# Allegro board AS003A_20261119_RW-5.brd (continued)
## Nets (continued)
D11210: D112.10 SITE1.T30(D5C1_ALERT0_N)
D11211: D112.11 SITE1.F25(PCIE_PERST_N)
D11212: D112.12 SITE1.P30(D5C1_CB6_A)
D11213: D112.13 K3.4
D11214: D112.14 SITE1.L30(D5C1_CB0_A)
D11215: D112.15 K4.4
D11216: D112.16 SITE1.B8(GPIO[33])
D11301: D113.01 R144.2
D11302: D113.02 R138.2
D11303: D113.03 R143.2
D11304: D113.04 R137.2
D11305: D113.05 R140.2
D11306: D113.06 R141.2
D11307: D113.07 R139.2
D11308: D113.08 R142.2
D11309: D113.09 R152.2
D11310: D113.10 R145.2
D11311: D113.11 R151.2
D11312: D113.12 R146.2
D11313: D113.13 R148.2
D11314: D113.14 R149.2
D11315: D113.15 R147.2
D11316: D113.16 R150.2
D11401: D114.01 SITE1.H30(D5C1_DQ19_A)
D11402: D114.02 SITE1.D32(D5C1_DQS5_A_T)
D11403: D114.03 SITE1.E30(D5C1_DQ5_A)
D11404: D114.04 SITE1.D31(D5C1_DQS5_A_C)
D11405: D114.05 SITE1.C30(D5C1_DQ3_A)
D11406: D114.06 SITE1.B31(D5C1_DQS0_A_T)
D11407: D114.07 SITE1.C27(D5C1_DQ11_A)
D11408: D114.08 SITE1.B32(D5C1_DQS0_A_C)
D11409: D114.09 SITE1.C8(GPIO[32])
D11410: D114.10 SITE1.B28(D5C1_DQS1_A_T)
D11411: D114.11 SITE1.C6(D5C0_DQ20_B)
D11412: D114.12 SITE1.B29(D5C1_DQS1_A_C)
D11413: D114.13 SITE1.C3(D5C0_DQ28_B)
D11414: D114.14 SITE1.B5(D5C0_DQS7_B_T)
D11415: D114.15 SITE1.E3(D5C0_DQ26_B)
D11416: D114.16 SITE1.B4(D5C0_DQS7_B_C)
D11501: D115.01 SITE1.A29(D5C1_DQ8_A)
D11502: D115.02 SITE1.F30(D5C1_DQ16_A)
D11503: D115.03 SITE1.A27(D5C1_DQ9_A)
D11504: D115.04 SITE1.D30(D5C1_DQ6_A)
D11505: D115.05 SITE1.A8(GPIO[34])
D11506: D115.06 SITE1.C28(D5C1_DQ12_A)
D11507: D115.07 SITE1.B7(GPIO[38])
D11508: D115.08 SITE1.C26(GPIO[29])
D11509: D115.09 SITE1.F6(D5C0_DQ6_B)
D11510: D115.10 SITE1.D4(D5C0_DQS2_B_T)
D11511: D115.11 SITE1.C7(GPIO[37])
D11512: D115.12 SITE1.D5(D5C0_DQS2_B_C)
D11513: D115.13 SITE1.C5(D5C0_DQ19_B)
D11514: D115.14 SITE1.G5(D5C0_DQS5_B_T)
D11515: D115.15 SITE1.D3(D5C0_DQ25_B)
D11516: D115.16 SITE1.G4(D5C0_DQS5_B_C)
D11601: D116.01 TR2.2 TR3.2
D11602: D116.02 SITE1.A28(D5C1_DQ10_A)
D11603: D116.03 SITE1.A31(D5C1_DQ1_A)
D11604: D116.04 SITE1.A26(GPIO[31])
D11605: D116.05 SITE1.A32(D5C1_DQ2_A)
D11606: D116.06 SITE1.A7(GPIO[39])
D11607: D116.07 SITE1.A6(D5C0_DQ22_B)
D11608: D116.08 SITE1.A5(D5C0_DQ21_B)
D11609: D116.09 SITE1.A4(D5C0_DQ23_B)
D11610: D116.10 SITE1.A30(D5C1_DQ0_A)
D11611: D116.11 SITE1.F27(D5C1_DQ25_A)
D11612: D116.12 SITE1.AA30(D5C1_CA2_B)
D11613: D116.13 SITE1.AD30(D5C1_CS0_B_N)
D11614: D116.14 SITE1.C2(D5C0_DQ27_B)
D11615: D116.15 SITE1.AF30(D5C1_CS3_B_N)
D11616: D116.16 SITE1.J30(D5C1_DQ22_A)
D11701: D117.01 SITE1.AE5(D5C0_CS0_A_N)
D11702: D117.02 SITE1.AM4(D5C0_DQS4_A_T)
D11703: D117.03 SITE1.AF5(D5C0_CS2_A_N)
D11704: D117.04 SITE1.AL4(D5C0_DQS4_A_C)
D11705: D117.05 SITE1.AG5(D5C0_DQ26_A)
D11706: D117.06 SITE1.AL7(D5C0_DQS7_A_T)
D11707: D117.07 SITE1.AH6(D5C0_DQ13_A)
D11708: D117.08 SITE1.AM7(D5C0_DQS7_A_C)
D11709: D117.09 SITE1.AH8(D5C0_DQ11_A)
D11710: D117.10 SITE1.AM9(D5C0_DQS2_A_T)
D11711: D117.11 SITE1.AG11(GPIO[12])
D11712: D117.12 SITE1.AL9(D5C0_DQS2_A_C)
D11713: D117.13 SITE1.AH11(GPIO[13])
D11714: D117.14 SITE1.AL12(D5C0_DQS5_A_T)
D11715: D117.15 SITE1.AH12(GPIO[16])
D11716: D117.16 SITE1.AM12(D5C0_DQS5_A_C)
D11801: D118.01 SITE1.AJ13(GPIO[20])
D11802: D118.02 SITE1.J4(D5C0_DQS0_B_T)
D11803: D118.03 SITE1.AJ14(GPIO[23])
D11804: D118.04 SITE1.J5(D5C0_DQS0_B_C)
D11805: D118.05 SITE1.AJ15(SPI_SCS)
D11806: D118.06 SITE1.M5(D5C0_CK1_B_T)
D11807: D118.07 SITE1.AJ16(SPI_DOUT)
D11808: D118.08 SITE1.M4(D5C0_CK1_B_C)
D11809: D118.09 SITE1.AJ17(UART_RX)
D11810: D118.10 SITE1.P5(D5C0_CK0_B_T)
D11811: D118.11 SITE1.AJ18(GPIO[26])
D11812: D118.12 SITE1.P4(D5C0_CK0_B_C)
D11813: D118.13 SITE1.AJ19(GPIO[11])
D11814: D118.14 SITE1.T5(D5C0_CK2_B_T)
D11815: D118.15 SITE1.AJ20(GPIO[8])
D11816: D118.16 SITE1.T4(D5C0_CK2_B_C)
D11901: D119.01 SITE1.AE2(D5C0_CS1_A_N)
D11902: D119.02 SITE1.Y3(D5C0_CA10_A)
D11903: D119.03 SITE1.AG6(D5C0_DQ14_A)
D11904: D119.04 SITE1.AA3(D5C0_CA9_A)
D11905: D119.05 SITE1.AL3(D5C0_CB3_A)
D11906: D119.06 SITE1.AB3(D5C0_CA7_A)
D11907: D119.07 SITE1.AL6(D5C0_DQ22_A)
D11908: D119.08 SITE1.AD3(D5C0_CA3_A)
D11909: D119.09 SITE1.AL8(D5C0_DQ19_A)
D11910: D119.10 SITE1.AE3(D5C0_CA0_A)
D11911: D119.11 SITE1.AG10(D5C0_DQ10_A)
D11912: D119.12 SITE1.AF3(D5C0_CS3_A_N)
D11913: D119.13 SITE1.AL11(D5C0_DQ6_A)
D11914: D119.14 SITE1.AG3(D5C0_DQ28_A)
D11915: D119.15 SITE1.AL13(D5C0_DQ3_A)
D11916: D119.16 SITE1.AH3(D5C0_DQ27_A)
D12001: D120.01 SITE1.AC6(D5C0_ATBPAD)
D12002: D120.02 SITE1.AD5(D5C0_PWR_GOOD)
D12003: D120.03 SITE1.AA5(D5C0_CA12_B)
D12004: D120.04 K5.4
D12005: D120.05 SITE1.H6(D5C0_DQ4_B)
D12006: D120.06 SITE1.J6(D5C0_DQ1_B)
D12007: D120.07 SITE1.K1(D5C0_DQ8_B)
D12008: D120.08 SITE1.L1(D5C0_CB1_B)
D12009: D120.09 SITE1.N6(D5C0_CS0_B_N)
D12010: D120.10 SITE1.P6(D5C0_CA1_B)
D12011: D120.11 SITE1.R1(D5C0_CB4_B)
D12012: D120.12 SITE1.U1(D5C0_ODT1_NC)
D12013: D120.13 SITE1.V1(D5C0_ODT2_NC)
D12014: D120.14 SITE1.W1(D5C0_CA11_A)
D12015: D120.15 SITE1.AA6(D5C0_CA10_B)
D12016: D120.16 SITE1.AB6(D5C0_MEMRESET_N)
D12101: D121.01 SITE1.AH13(GPIO[19])
D12102: D121.02 SITE1.AM14(D5C0_DQS0_A_T)
D12103: D121.03 SITE1.AH14(GPIO[22])
D12104: D121.04 SITE1.AL14(D5C0_DQS0_A_C)
D12105: D121.05 SITE1.AH15(TEST_EN)
D12106: D121.06 SITE1.AM19(D5C1_DQS8_B_T)
D12107: D121.07 SITE1.AH16(SPI_DIN)
D12108: D121.08 SITE1.AL19(D5C1_DQS8_B_C)
D12109: D121.09 SITE1.AH17(UART_TX)
D12110: D121.10 SITE1.AL21(D5C1_DQS3_B_T)
D12111: D121.11 SITE1.AH18(GPIO[25])
D12112: D121.12 SITE1.AM21(D5C1_DQS3_B_C)
D12113: D121.13 SITE1.AH19(GPIO[10])
D12114: D121.14 SITE1.AM24(D5C1_DQS6_B_T)
D12115: D121.15 SITE1.AH20(GPIO[7])
D12116: D121.16 SITE1.AL24(D5C1_DQS6_B_C)
D12201: D122.01 SITE1.AJ21(GPIO[5])
D12202: D122.02 SITE1.V5(D5C0_CK3_B_T)
D12203: D122.03 SITE1.AJ22(GPIO[2])
D12204: D122.04 SITE1.V4(D5C0_CK3_B_C)
D12205: D122.05 SITE1.AJ23(D5C1_DQ23_B)
D12206: D122.06 SITE1.AJ4(D5C0_DQS3_A_T)
D12207: D122.07 SITE1.AJ27(D5C1_DQ16_B)
D12208: D122.08 SITE1.AH4(D5C0_DQS3_A_C)
D12209: D122.09 SITE1.AJ28(D5C1_DQ7_B)
D12210: D122.10 SITE1.AH7(D5C0_DQS6_A_T)
D12211: D122.11 SITE1.AG29(D5C1_DQ6_B)
D12212: D122.12 SITE1.AJ7(D5C0_DQS6_A_C)
D12213: D122.13 SITE1.AE29(D5C1_ODT3_NC)
D12214: D122.14 SITE1.AJ9(D5C0_DQS1_A_T)
D12215: D122.15 SITE1.AD29(D5C1_CA13_A)
D12216: D122.16 SITE1.AH9(D5C0_DQS1_A_C)
D12301: D123.01 SITE1.AG15(DDR_SCL)
D12302: D123.02 SITE1.AK3(D5C0_CB4_A)
D12303: D123.03 SITE1.AG16(SPI_SCK)
D12304: D123.04 SITE1.AK4(D5C0_CB1_A)
D12305: D123.05 SITE1.AL17(SLV_SDA)
D12306: D123.06 SITE1.AK5(D5C0_CB2_A)
D12307: D123.07 SITE1.AG18(GPIO[24])
D12308: D123.08 SITE1.AK6(D5C0_DQ23_A)
D12309: D123.09 SITE1.AL20(D5C1_DQ28_B)
D12310: D123.10 SITE1.AK8(D5C0_DQ20_A)
D12311: D123.11 SITE1.AL22(D5C1_DQ25_B)
D12312: D123.12 SITE1.AK9(D5C0_DQ17_A)
D12313: D123.13 SITE1.AG23(D5C1_DQ21_B)
D12314: D123.14 SITE1.AK10(D5C0_DQ18_A)
D12315: D123.15 SITE1.AL25(D5C1_DQ12_B)
D12316: D123.16 SITE1.AK11(D5C0_DQ7_A)
D12401: D124.01 SITE1.AC1(D5C0_CA5_A)
D12402: D124.02 SITE1.AE6(D5C0_CA2_A)
D12403: D124.03 SITE1.AF6(D5C0_ALERT1_N)
D12404: D124.04 SITE1.AG1(D5C0_DQ30_A)
D12405: D124.05 SITE1.AH1(D5C0_DQ29_A)
D12406: D124.06 SITE1.AJ1(D5C0_DQ31_A)
D12407: D124.07 SITE1.AK1(D5C0_CB7_A)
D12408: D124.08 SITE1.AL1(D5C0_CB6_A)
D12409: D124.09 SITE1.AM1(D5C0_CB5_A)
D12410: D124.10 SITE1.AM5(D5C0_CB0_A)
D12411: D124.11 SITE1.AM6(D5C0_DQ21_A)
D12412: D124.12 SITE1.AG8(D5C0_DQ12_A)
D12413: D124.13 SITE1.AG9(D5C0_DQ9_A)
D12414: D124.14 SITE1.AM10(D5C0_DQ16_A)
D12415: D124.15 SITE1.AM11(D5C0_DQ5_A)
D12416: D124.16 SITE1.AG13(GPIO[18])
D12501: D125.01 SITE1.D7(GPIO[36])
D12502: D125.02 SITE1.B2(D5C0_DQS8_B_T)
D12503: D125.03 SITE1.A2(D5C0_DQ30_B)
D12504: D125.04 SITE1.B1(D5C0_DQS8_B_C)
D12505: D125.05 SITE1.A1(D5C0_DQ29_B)
D12506: D125.06 SITE1.D1(D5C0_DQS3_B_T)
D12507: D125.07 SITE1.E1(D5C0_DQ24_B)
D12508: D125.08 SITE1.D2(D5C0_DQS3_B_C)
D12509: D125.09 SITE1.F1(D5C0_DQ13_B)
D12510: D125.10 SITE1.G2(D5C0_DQS6_B_T)
D12511: D125.11 SITE1.E7(GPIO[35])
D12512: D125.12 SITE1.G1(D5C0_DQS6_B_C)
D12513: D125.13 SITE1.E6(D5C0_DQ18_B)
D12514: D125.14 SITE1.J1(D5C0_DQS1_B_T)
D12515: D125.15 SITE1.F5(D5C0_DQ5_B)
D12516: D125.16 SITE1.J2(D5C0_DQS1_B_C)
D12601: D126.01 SITE1.J3(D5C0_DQ9_B)
D12602: D126.02 SITE1.M2(D5C0_DQS4_B_T)
D12603: D126.03 SITE1.E4(D5C0_DQ16_B)
D12604: D126.04 SITE1.M1(D5C0_DQS4_B_C)
D12605: D126.05 SITE1.K4(D5C0_DQ0_B)
D12606: D126.06 SITE1.P2(D5C0_DQS9_B_T)
D12607: D126.07 SITE1.N4(D5C0_PAR_B)
D12608: D126.08 SITE1.P1(D5C0_DQS9_B_C)
D12609: D126.09 SITE1.U4(D5C0_CA4_B)
D12610: D126.10 SITE1.Y1(D5C0_CK2_A_T)
D12611: D126.11 SITE1.Y4(D5C0_CA11_B)
D12612: D126.12 SITE1.Y2(D5C0_CK2_A_C)
D12613: D126.13 SITE1.AB4(D5C0_ALERT0_N)
D12614: D126.14 SITE1.AB2(D5C0_CK1_A_T)
D12615: D126.15 SITE1.AD4(D5C0_CA4_A)
D12616: D126.16 SITE1.AB1(D5C0_CK1_A_C)
D12701: D127.01 SITE1.H2(D5C0_DQ11_B)
D12702: D127.02 SITE1.D6(D5C0_DQ17_B)
D12703: D127.03 SITE1.L3(D5C0_CB3_B)
D12704: D127.04 SITE1.F4(D5C0_DQ7_B)
D12705: D127.05 SITE1.P3(D5C0_CB5_B)
D12706: D127.06 SITE1.M6(D5C0_CS2_B_N)
D12707: D127.07 SITE1.T3(D5C0_CID1_NC)
D12708: D127.08 SITE1.T6(D5C0_CA2_B)
D12709: D127.09 SITE1.V3(D5C0_CA13_A)
D12710: D127.10 SITE1.W6(D5C0_CA7_B)
D12711: D127.11 SITE1.T2(D5C0_CID0_NC)
D12712: D127.12 SITE1.AA4(D5C0_CA13_B)
D12713: D127.13 SITE1.W2(D5C0_CA12_A)
D12714: D127.14 SITE1.AC4(D5C0_PAR_A)
D12715: D127.15 SITE1.AC2(D5C0_CA6_A)
D12716: D127.16 SITE1.AE4(D5C0_CA1_A)
D12801: D128.01 SITE1.F2(D5C0_DQ14_B)
D12802: D128.02 SITE1.K3(D5C0_DQ10_B)
D12803: D128.03 SITE1.K6(D5C0_DQ2_B)
D12804: D128.04 SITE1.N3(D5C0_CB0_B)
D12805: D128.05 SITE1.L2(D5C0_CB2_B)
D12806: D128.06 SITE1.R3(D5C0_CB6_B)
D12807: D128.07 SITE1.N2(D5C0_CB7_B)
D12808: D128.08 SITE1.U3(D5C0_CID2_NC)
D12809: D128.09 SITE1.R6(D5C0_CA0_B)
D12810: D128.10 SITE1.W3(D5C0_ODT0_NC)
D12811: D128.11 SITE1.H3(D5C0_DQ12_B)
D12812: D128.12 SITE1.U2(D5C0_ODT3_NC)
D12813: D128.13 SITE1.F3(D5C0_DQ15_B)
D12814: D128.14 SITE1.AA2(D5C0_CA8_A)
D12815: D128.15 SITE1.AG22(GPIO[0])
D12816: D128.16 SITE1.AG4(D5C0_DQ25_A)
D12901: D129.01 SITE1.H5(D5C0_DQ3_B)
D12902: D129.02 SITE1.AD1(D5C0_CK0_A_T)
D12903: D129.03 SITE1.L5(D5C0_CS1_B_N)
D12904: D129.04 SITE1.AD2(D5C0_CK0_A_C)
D12905: D129.05 SITE1.L6(D5C0_CS3_B_N)
D12906: D129.06 SITE1.AF2(D5C0_CK3_A_T)
D12907: D129.07 SITE1.R5(D5C0_CA3_B)
D12908: D129.08 SITE1.AF1(D5C0_CK3_A_C)
D12909: D129.09 SITE1.U6(D5C0_CA5_B)
D12910: D129.10 SITE1.AH2(D5C0_DQS8_A_T)
D12911: D129.11 SITE1.V6(D5C0_CA6_B)
D12912: D129.12 SITE1.AJ2(D5C0_DQS8_A_C)
D12913: D129.13 SITE1.W5(D5C0_CA9_B)
D12914: D129.14 SITE1.AL2(D5C0_DQS9_A_T)
D12915: D129.15 SITE1.Y5(D5C0_CA8_B)
D12916: D129.16 SITE1.AM2(D5C0_DQS9_A_C)
D13001: D130.01 SITE1.AJ5(D5C0_DQ24_A)
D13002: D130.02 SITE1.AJ6(D5C0_DQ15_A)
D13003: D130.03 SITE1.AJ10(D5C0_DQ8_A)
D13004: D130.04 SITE1.AJ11(GPIO[14])
D13005: D130.05 SITE1.AJ12(GPIO[17])
D13006: D130.06 SITE1.A3(D5C0_DQ31_B)
D13007: D130.07
D13008: D130.08
D13009: D130.09
D13010: D130.10
D13011: D130.11
D13012: D130.12
D13013: D130.13
D13014: D130.14
D13015: D130.15
D13016: D130.16
D13101: D131.01
D13102: D131.02
D13103: D131.03
D13104: D131.04
D13105: D131.05
D13106: D131.06
D13107: D131.07
D13108: D131.08
D13109: D131.09
D13110: D131.10
D13111: D131.11
D13112: D131.12
D13113: D131.13
D13114: D131.14
D13115: D131.15
D13116: D131.16
D13201: D132.01
D13202: D132.02
D13203: D132.03
D13204: D132.04
D13205: D132.05
D13206: D132.06
D13207: D132.07
D13208: D132.08
D13209: D132.09
D13210: D132.10
D13211: D132.11
D13212: D132.12
D13213: D132.13
D13214: D132.14
D13215: D132.15
D13216: D132.16
D21701: D217.01
D21702: D217.02
D21703: D217.03
D21704: D217.04
D21705: D217.05
D21706: D217.06
D21707: D217.07
D21708: D217.08
D21709: D217.09
D21710: D217.10
D21711: D217.11
D21712: D217.12
D21713: D217.13
D21714: D217.14
D21715: D217.15
D21716: D217.16
D21801: D218.01
D21802: D218.02
D21803: D218.03
D21804: D218.04
D21805: D218.05
D21806: D218.06
D21807: D218.07
D21808: D218.08
D21809: D218.09
D21810: D218.10
D21811: D218.11
D21812: D218.12
D21813: D218.13
D21814: D218.14
D21815: D218.15
D21816: D218.16
D21901: D219.01
D21902: D219.02
D21903: D219.03
D21904: D219.04
D21905: D219.05
D21906: D219.06
D21907: D219.07
D21908: D219.08
D21909: D219.09
D21910: D219.10
D21911: D219.11
D21912: D219.12
D21913: D219.13
D21914: D219.14
D21915: D219.15
D21916: D219.16
D22001: D220.01
D22002: D220.02
D22003: D220.03
D22004: D220.04
D22005: D220.05
D22006: D220.06
D22007: D220.07
D22008: D220.08
D22009: D220.09
D22010: D220.10
D22011: D220.11
D22012: D220.12
D22013: D220.13
D22014: D220.14
D22015: D220.15
D22016: D220.16
D22101: D221.01
D22102: D221.02
D22103: D221.03
D22104: D221.04
D22105: D221.05
D22106: D221.06
D22107: D221.07
D22108: D221.08
D22109: D221.09
D22110: D221.10
D22111: D221.11
D22112: D221.12
D22113: D221.13
D22114: D221.14
D22115: D221.15
D22116: D221.16
D22201: D222.01
D22202: D222.02
D22203: D222.03
D22204: D222.04
D22205: D222.05
D22206: D222.06
D22207: D222.07
D22208: D222.08
D22209: D222.09
D22210: D222.10
D22211: D222.11
D22212: D222.12
D22213: D222.13
D22214: D222.14
D22215: D222.15
D22216: D222.16
D22301: D223.01
D22302: D223.02
D22303: D223.03
D22304: D223.04
D22305: D223.05
D22306: D223.06
D22307: D223.07
D22308: D223.08
D22309: D223.09
D22310: D223.10
D22311: D223.11
D22312: D223.12
D22313: D223.13
D22314: D223.14
D22315: D223.15
D22316: D223.16
D22401: D224.01
D22402: D224.02
D22403: D224.03
D22404: D224.04
D22405: D224.05
D22406: D224.06
D22407: D224.07
D22408: D224.08
D22409: D224.09
D22410: D224.10
D22411: D224.11
D22412: D224.12
D22413: D224.13
D22414: D224.14
D22415: D224.15
D22416: D224.16
D30101: D301.01
D30102: D301.02
D30103: D301.03
D30104: D301.04
D30105: D301.05
D30106: D301.06
D30107: D301.07
D30108: D301.08
D30109: D301.09
D30110: D301.10
D30111: D301.11
D30112: D301.12
D30113: D301.13
D30114: D301.14
D30115: D301.15
D30116: D301.16
D30201: D302.01
D30202: D302.02
D30203: D302.03
D30204: D302.04
D30205: D302.05
D30206: D302.06
D30207: D302.07
D30208: D302.08
D30209: D302.09
D30210: D302.10
D30211: D302.11
D30212: D302.12
D30213: D302.13
D30214: D302.14
D30215: D302.15
D30216: D302.16
D30301: D303.01
D30302: D303.02
D30303: D303.03
D30304: D303.04
D30305: D303.05
D30306: D303.06
D30307: D303.07
D30308: D303.08
D30309: D303.09
D30310: D303.10
D30311: D303.11
D30312: D303.12
D30313: D303.13
D30314: D303.14
D30315: D303.15
D30316: D303.16
D30401: D304.01
D30402: D304.02
D30403: D304.03
D30404: D304.04
D30405: D304.05
D30406: D304.06
D30407: D304.07
D30408: D304.08
D30409: D304.09
D30410: D304.10
D30411: D304.11
D30412: D304.12
D30413: D304.13
D30414: D304.14
D30415: D304.15
D30416: D304.16
D30501: D305.01
D30502: D305.02
D30503: D305.03
D30504: D305.04
D30505: D305.05
D30506: D305.06
D30507: D305.07
D30508: D305.08
D30509: D305.09
D30510: D305.10
D30511: D305.11
D30512: D305.12
D30513: D305.13
D30514: D305.14
D30515: D305.15
D30516: D305.16
D30601: D306.01
D30602: D306.02
D30603: D306.03
D30604: D306.04
D30605: D306.05
D30606: D306.06
D30607: D306.07
D30608: D306.08
D30609: D306.09
D30610: D306.10
D30611: D306.11
D30612: D306.12
D30613: D306.13
D30614: D306.14
D30615: D306.15
D30616: D306.16
D30701: D307.01
D30702: D307.02
D30703: D307.03
D30704: D307.04
D30705: D307.05
D30706: D307.06
D30707: D307.07
D30708: D307.08
D30709: D307.09
D30710: D307.10
D30711: D307.11
D30712: D307.12
D30713: D307.13
D30714: D307.14
D30715: D307.15
D30716: D307.16
D30801: D308.01
D30802: D308.02
D30803: D308.03
D30804: D308.04
D30805: D308.05
D30806: D308.06
D30807: D308.07
D30808: D308.08
D30809: D308.09
D30810: D308.10
D30811: D308.11
D30812: D308.12
D30813: D308.13
D30814: D308.14
D30815: D308.15
D30816: D308.16
D30901: D309.01
D30902: D309.02
D30903: D309.03
D30904: D309.04
D30905: D309.05
D30906: D309.06
D30907: D309.07
D30908: D309.08
D30909: D309.09
D30910: D309.10
D30911: D309.11
D30912: D309.12
D30913: D309.13
D30914: D309.14
D30915: D309.15
D30916: D309.16
D31001: D310.01
D31002: D310.02
D31003: D310.03
D31004: D310.04
D31005: D310.05
D31006: D310.06
D31007: D310.07
D31008: D310.08
D31009: D310.09
D31010: D310.10
D31011: D310.11
D31012: D310.12
D31013: D310.13
D31014: D310.14
D31015: D310.15
D31016: D310.16
D31101: D311.01
D31102: D311.02
D31103: D311.03
D31104: D311.04
D31105: D311.05
D31106: D311.06
D31107: D311.07
D31108: D311.08
D31109: D311.09
D31110: D311.10
D31111: D311.11
D31112: D311.12
D31113: D311.13
D31114: D311.14
D31115: D311.15
D31116: D311.16
D31201: D312.01
D31202: D312.02
D31203: D312.03
D31204: D312.04
D31205: D312.05
D31206: D312.06
D31207: D312.07
D31208: D312.08
D31209: D312.09
D31210: D312.10
D31211: D312.11
D31212: D312.12
D31213: D312.13
D31214: D312.14
D31215: D312.15
D31216: D312.16
D31301: D313.01
D31302: D313.02
D31303: D313.03
D31304: D313.04
D31305: D313.05
D31306: D313.06
D31307: D313.07
D31308: D313.08
D31309: D313.09
D31310: D313.10
D31311: D313.11
D31312: D313.12
D31313: D313.13
D31314: D313.14
D31315: D313.15
D31316: D313.16
D31401: D314.01
D31402: D314.02
D31403: D314.03
D31404: D314.04
D31405: D314.05
D31406: D314.06
D31407: D314.07
D31408: D314.08
D31409: D314.09
D31410: D314.10
D31411: D314.11
D31412: D314.12
D31413: D314.13
D31414: D314.14
D31415: D314.15
D31416: D314.16
D31501: D315.01
D31502: D315.02
D31503: D315.03
D31504: D315.04
D31505: D315.05
D31506: D315.06
D31507: D315.07
D31508: D315.08
D31509: D315.09
D31510: D315.10
D31511: D315.11
D31512: D315.12
D31513: D315.13
D31514: D315.14
D31515: D315.15
D31516: D315.16
D31601: D316.01
D31602: D316.02
D31603: D316.03
D31604: D316.04
D31605: D316.05
D31606: D316.06
D31607: D316.07
D31608: D316.08
D31609: D316.09
D31610: D316.10
D31611: D316.11
D31612: D316.12
D31613: D316.13
D31614: D316.14
D31615: D316.15
D31616: D316.16
D31701: D317.01
D31702: D317.02
D31703: D317.03
D31704: D317.04
D31705: D317.05
D31706: D317.06
D31707: D317.07
D31708: D317.08
D31709: D317.09
D31710: D317.10
D31711: D317.11
D31712: D317.12
D31713: D317.13
D31714: D317.14
D31715: D317.15
D31716: D317.16
D31801: D318.01
D31802: D318.02
D31803: D318.03
D31804: D318.04
D31805: D318.05
D31806: D318.06
D31807: D318.07
D31808: D318.08
D31809: D318.09
D31810: D318.10
D31811: D318.11
D31812: D318.12
D31813: D318.13
D31814: D318.14
D31815: D318.15
D31816: D318.16
D31901: D319.01
D31902: D319.02
D31903: D319.03
D31904: D319.04
D31905: D319.05
D31906: D319.06
D31907: D319.07
D31908: D319.08
D31909: D319.09
D31910: D319.10
D31911: D319.11
D31912: D319.12
D31913: D319.13
D31914: D319.14
D31915: D319.15
D31916: D319.16
D32001: D320.01
D32002: D320.02
D32003: D320.03
D32004: D320.04
D32005: D320.05
D32006: D320.06
D32007: D320.07
D32008: D320.08
D32009: D320.09
D32010: D320.10
D32011: D320.11
D32012: D320.12
D32013: D320.13
D32014: D320.14
D32015: D320.15
D32016: D320.16
D32101: D321.01
D32102: D321.02
D32103: D321.03
D32104: D321.04
D32105: D321.05
D32106: D321.06
D32107: D321.07
D32108: D321.08
D32109: D321.09
D32110: D321.10
D32111: D321.11
D32112: D321.12
D32113: D321.13
D32114: D321.14
D32115: D321.15
D32116: D321.16
D32201: D322.01
D32202: D322.02
D32203: D322.03
D32204: D322.04
D32205: D322.05
D32206: D322.06
D32207: D322.07
D32208: D322.08
D32209: D322.09
D32210: D322.10
D32211: D322.11
D32212: D322.12
D32213: D322.13
D32214: D322.14
D32215: D322.15
D32216: D322.16
D32301: D323.01
D32302: D323.02
D32303: D323.03
D32304: D323.04
D32305: D323.05
D32306: D323.06
D32307: D323.07
D32308: D323.08
D32309: D323.09
D32310: D323.10
D32311: D323.11
D32312: D323.12
D32313: D323.13
D32314: D323.14
D32315: D323.15
D32316: D323.16
GPDPS1_1F: DPS1.A03 DPS1.B03 DPS1.C03 R224.2 R225.2 R226.2 R232.2
GPDPS1_1GRD: DPS1.B02
GPDPS1_1GS: DPS1.A02 R216.2
GPDPS1_1S: DPS1.C02 R231.2
GPDPS1_2F: DPS1.A07 DPS1.B07 DPS1.C07 R70.2
GPDPS1_2GRD: DPS1.B06
GPDPS1_2GS: DPS1.A06 R67.2
GPDPS1_2S: DPS1.C06 R71.2
GPDPS1_3F: DPS1.A13 DPS1.B13 DPS1.C13 R5.2
GPDPS1_3GRD: DPS1.B12
GPDPS1_3GS: DPS1.A12 R4.2
GPDPS1_3S: DPS1.C12 R6.2
GPDPS1_4F: DPS1.A17 DPS1.B17 DPS1.C17 R10.2
GPDPS1_4GRD: DPS1.B16
GPDPS1_4GS: DPS1.A16 R7.2
GPDPS1_4S: DPS1.C16 R11.2
GPDPS1_TR+: DPS1.A09
GPDPS1_TRVB-: DPS1.B09 SB1.2
GPDPS1_VB+: DPS1.C09
GPDPS2_1F: DPS2.A03 DPS2.B03 DPS2.C03 R16.2 R162.2
GPDPS2_1GRD: DPS2.B02
GPDPS2_1GS: DPS2.A02 R13.2
GPDPS2_1S: DPS2.C02 R17.2
GPDPS2_2F: DPS2.A07 DPS2.B07 DPS2.C07 R22.2
GPDPS2_2GRD: DPS2.B06
GPDPS2_2GS: DPS2.A06 R20.2
GPDPS2_2S: DPS2.C06 R23.2
GPDPS2_3F: DPS2.A13 DPS2.B13 DPS2.C13 R52.2 R64.2 R189.2 R194.2
GPDPS2_3GRD: DPS2.B12
GPDPS2_3GS: DPS2.A12 R62.2 R186.2 R191.2
GPDPS2_3S: DPS2.C12 R65.2
GPDPS2_4F: DPS2.A17 DPS2.B17 DPS2.C17 R204.2 R205.2 R206.2 R211.2
GPDPS2_4GRD: DPS2.B16
GPDPS2_4GS: DPS2.A16 R197.2
GPDPS2_4S: DPS2.C16 R212.2
GPDPS2_TR+: DPS2.A09
GPDPS2_TRVB-: DPS2.B09 SB13.2
GPDPS2_VB+: DPS2.C09
GPDPS3_1F: DPS3.A03 DPS3.B03 DPS3.C03 R77.2 R168.2 R169.2 R170.2
GPDPS3_1GRD: DPS3.B02
GPDPS3_1GS: DPS3.A02 R73.2
GPDPS3_1S: DPS3.C02 R76.2
GPDPS3_2F: DPS3.A07 DPS3.B07 DPS3.C07 R28.2 R34.2 R163.2 R164.2
GPDPS3_2GRD: DPS3.B06
GPDPS3_2GS: DPS3.A06 R26.2
GPDPS3_2S: DPS3.C06 R29.2
GPDPS3_3F: DPS3.A13 DPS3.B13 DPS3.C13 R40.2 R46.2
GPDPS3_3GRD: DPS3.B12
GPDPS3_3GS: DPS3.A12 R38.2
GPDPS3_3S: DPS3.C12 R41.2
GPDPS3_4F: DPS3.A17 DPS3.B17 DPS3.C17 R58.2
GPDPS3_4GRD: DPS3.B16
GPDPS3_4GS: DPS3.A16 R56.2
GPDPS3_4S: DPS3.C16 R59.2
GPDPS3_TR+: DPS3.A09
GPDPS3_TRVB-: DPS3.B09 SB14.2
GPDPS3_VB+: DPS3.C09
GPDPS4_1F: DPS4.A03 DPS4.B03 DPS4.C03
GPDPS4_1GRD: DPS4.B02
GPDPS4_1GS: DPS4.A02
GPDPS4_1S: DPS4.C02
GPDPS4_2F: DPS4.A07 DPS4.B07 DPS4.C07
GPDPS4_2GRD: DPS4.B06
GPDPS4_2GS: DPS4.A06
GPDPS4_2S: DPS4.C06
GPDPS4_3F: DPS4.A13 DPS4.B13 DPS4.C13
GPDPS4_3GRD: DPS4.B12
GPDPS4_3GS: DPS4.A12
GPDPS4_3S: DPS4.C12
GPDPS4_4F: DPS4.A17 DPS4.B17 DPS4.C17
GPDPS4_4GRD: DPS4.B16
GPDPS4_4GS: DPS4.A16
GPDPS4_4S: DPS4.C16
GPDPS4_TR+: DPS4.A09
GPDPS4_TRVB-: DPS4.B09 SB16.2
GPDPS4_VB+: DPS4.C09
GPDPS7_1F: DPS7.A03 DPS7.B03 DPS7.C03
GPDPS7_1GRD: DPS7.B02
GPDPS7_1GS: DPS7.A02
GPDPS7_1S: DPS7.C02
GPDPS7_2F: DPS7.A07 DPS7.B07 DPS7.C07
GPDPS7_2GRD: DPS7.B06
GPDPS7_2GS: DPS7.A06
GPDPS7_2S: DPS7.C06
GPDPS7_3F: DPS7.A13 DPS7.B13 DPS7.C13
GPDPS7_3GRD: DPS7.B12
GPDPS7_3GS: DPS7.A12
GPDPS7_3S: DPS7.C12
GPDPS7_4F: DPS7.A17 DPS7.B17 DPS7.C17
GPDPS7_4GRD: DPS7.B16
GPDPS7_4GS: DPS7.A16
GPDPS7_4S: DPS7.C16
GPDPS7_TR+: DPS7.A09
GPDPS7_TRVB-: DPS7.B09 SB19.2
GPDPS7_VB+: DPS7.C09
GPDPS8_1F: DPS8.A03 DPS8.B03 DPS8.C03
GPDPS8_1GRD: DPS8.B02
GPDPS8_1GS: DPS8.A02
GPDPS8_1S: DPS8.C02
GPDPS8_2F: DPS8.A07 DPS8.B07 DPS8.C07
GPDPS8_2GRD: DPS8.B06
GPDPS8_2GS: DPS8.A06
GPDPS8_2S: DPS8.C06
GPDPS8_3F: DPS8.A13 DPS8.B13 DPS8.C13
GPDPS8_3GRD: DPS8.B12
GPDPS8_3GS: DPS8.A12
GPDPS8_3S: DPS8.C12
GPDPS8_4F: DPS8.A17 DPS8.B17 DPS8.C17
GPDPS8_4GRD: DPS8.B16
GPDPS8_4GS: DPS8.A16
GPDPS8_4S: DPS8.C16
GPDPS8_TR+: DPS8.A09
GPDPS8_TRVB-: DPS8.B09 SB15.2
GPDPS8_VB+: DPS8.C09
S1_CBIT001: DV2.2(B) K1.9(V-)
S1_CBIT002: DV3.2(B) K2.9(V-)
S1_CBIT003: DV4.2(B) K3.8(V-)
S1_CBIT004: DV5.2(B) K4.8(V-)
S1_CBIT005: DV6.2(B) K5.8(V-)
S1_CBIT006: DV7.2(B) K6.8(V-)
S1_CBIT007: DV8.2(B) K7.8(V-)
S1_CBIT008: DV9.2(B) K8.8(V-)
S1_CBIT009: DV10.2(B) K9.8(V-)
S1_CBIT010: DV11.2(B) K10.8(V-)
S1_CBIT011: DV12.2(B) K11.8(V-)
S1_CBIT012: DV13.2(B) K12.8(V-)
S1_CSDPS001F: R2.2
S1_CSDPS001GS: R3.2
S1_CSDPS001S: R1.2
S1_CSDPS002F: R9.2
S1_CSDPS002GS: R8.2
S1_CSDPS002S: R12.2
S1_CSDPS003-1F: R15.2 R153.2
S1_CSDPS003-1GS: R14.2
S1_CSDPS003-1S: R18.2
S1_CSDPS004-1F: R21.2
S1_CSDPS004-1GS: R19.2
S1_CSDPS004-1S: R24.2
S1_CSDPS005-1F: R27.2 R154.2
S1_CSDPS005-1GS: R25.2
S1_CSDPS005-1S: R30.2
S1_CSDPS006-1F: R33.2 R155.2
S1_CSDPS006-1GS: R31.2
S1_CSDPS006-1S: R36.2
S1_CSDPS007-1F: R39.2
S1_CSDPS007-1GS: R37.2
S1_CSDPS007-1S: R42.2
S1_CSDPS008-1F: R45.2
S1_CSDPS008-1GS: R43.2
S1_CSDPS008-1S: R48.2
S1_CSDPS009F: R51.2
S1_CSDPS009GS: R49.2
S1_CSDPS009S: R54.2
S1_CSDPS010-1F: R57.2
S1_CSDPS010-1GS: R55.2
S1_CSDPS010-1S: R60.2
S1_CSDPS011F: R63.2
S1_CSDPS011GS: R61.2
S1_CSDPS011S: R66.2
S1_CSDPS012F: R69.2
S1_CSDPS012GS: R68.2
S1_CSDPS012S: R72.2
S1_CSDPS013-1F: R75.2 R156.2 R157.2 R158.2
S1_CSDPS013-1GS: R74.2
S1_CSDPS013-1S: R78.2
S1_CSDPS014-1F: R198.2 R199.2 R200.2 R210.2
S1_CSDPS014-1GS: R196.2 R217.2
S1_CSDPS014-1S: R213.2
S1_CSDPS015-1F: R218.2 R219.2 R220.2 R230.2
S1_CSDPS015-1S: R233.2
S1_CSDPS016F: R187.2
S1_CSDPS016GS: R188.2
S1_CSDPS016S: R190.2
S1_CSDPS017F: R192.2
S1_CSDPS017GS: R193.2
S1_CSDPS017S: R195.2
S1_D5C0_ZQPAD: R112.1 R113.1 SITE1.AC5(D5C0_ZQPAD)
S1_D5C0_ZQPAD_A: K5.3 R113.2
S1_D5C1_ZQPAD: R114.1 R115.1 SITE1.M27(D5C1_ZQPAD)
S1_D5C1_ZQPAD_A: K6.3 R115.2
S1_DPS1: C81.1 C82.1 C216.1 C217.1 C218.1 C219.1 C220.1 R57.1 R58.1 R59.1 R60.1 S1_DPS1.1(TP) SITE1.T12(VAA[1]) SITE1.T22(VAA[2])
S1_DPS3: C83.1 C221.1 C222.1 C223.1 C224.1 C225.1 R63.1 R64.1 R65.1 R66.1 S1_DPS3.1(TP) SITE1.AE19(VCC18V_POR)
S1_DPS4: C84.1 C226.1 C227.1 C228.1 C229.1 C230.1 R69.1 R70.1 R71.1 R72.1 S1_DPS4.1(TP) SITE1.V16(VCC18V_TSENSOR)
S1_DPS5: C58.1 C59.1 C60.1 C61.1 C62.1 C63.1 C64.1 C65.1 C66.1 C67.1 C68.1 C69.1 C201.1 C202.1 C203.1 C204.1 C205.1 R39.1 R40.1 R41.1 R42.1 S1_DPS5.1(TP) SITE1.AA11(VDD_DDR_CORE_0[1]) SITE1.AB12(VDD_DDR_CORE_0[2]) SITE1.AC11(VDD_DDR_CORE_0[3]) SITE1.AD12(VDD_DDR_CORE_0[4]) SITE1.N11(VDD_DDR_CORE_0[5]) SITE1.P12(VDD_DDR_CORE_0[6]) SITE1.R11(VDD_DDR_CORE_0[7]) SITE1.R13(VDD_DDR_CORE_0[8]) SITE1.U11(VDD_DDR_CORE_0[9]) SITE1.V12(VDD_DDR_CORE_0[10]) SITE1.W11(VDD_DDR_CORE_0[11]) SITE1.Y12(VDD_DDR_CORE_0[12])
S1_DPS7: C70.1 C71.1 C72.1 C73.1 C74.1 C75.1 C76.1 C77.1 C78.1 C79.1 C80.1 C206.1 C207.1 C208.1 C209.1 C210.1 R45.1 R46.1 R48.1 S1_DPS7.1(TP) SITE1.AA21(VDD_DDR_CORE_1[1]) SITE1.AB22(VDD_DDR_CORE_1[2]) SITE1.AC21(VDD_DDR_CORE_1[3]) SITE1.AD22(VDD_DDR_CORE_1[4]) SITE1.N21(VDD_DDR_CORE_1[5]) SITE1.P22(VDD_DDR_CORE_1[6]) SITE1.R21(VDD_DDR_CORE_1[7]) SITE1.U21(VDD_DDR_CORE_1[8]) SITE1.V22(VDD_DDR_CORE_1[9]) SITE1.W21(VDD_DDR_CORE_1[10]) SITE1.Y22(VDD_DDR_CORE_1[11])
S1_DPS9: C1.1 C2.1 C3.1 C4.1 C5.1 C6.1 R1.1 R2.1 R5.1 R6.1 S1_DPS9.1(TP) SITE1.U17(VDDHV)
S1_DPS10: C7.1 C8.1 C9.1 C10.1 C11.1 C12.1 C13.1 C14.1 R9.1 R10.1 R11.1 R12.1 S1_DPS10.1(TP) SITE1.AE13(VDDPST[1]) SITE1.AE15(VDDPST[2]) SITE1.AE17(VDDPST[3])
S1_DPS11: BD18.1 C249.1 C250.1 C291.1 C292.1 C293.1 C294.1 C295.1 C416.1 C417.1 C467.1 C468.1 C469.1 K10.3 K11.3 K12.3 R187.1 R189.1 R190.1 R253.2 R254.2 S1_DPS11.1(TP) U1.6(VDD) U2.6(VDD) U4.6(VDD)
S1_DPS12: C251.1 C296.1 C297.1 C298.1 C299.1 C300.1 C418.1 OSC1.4(VDD) R116.2 R192.1 R194.1 R195.1 S1_DPS12.1(TP)
S1_DPS17: BD13.1 BD14.1 C26.1 C27.1 C28.1 C29.1 C30.1 C31.1 C32.1 C33.1 C34.1 C35.1 C36.1 C37.1 C181.1 C182.1 C183.1 C184.1 C185.1 C286.1 R17.1 R18.1 S1_DPS17.1(TP) SITE1.L13(VDD_PCIE[1]) SITE1.L15(VDD_PCIE[2]) SITE1.L17(VDD_PCIE[3]) SITE1.L19(VDD_PCIE[4]) SITE1.M12(VDD_PCIE[5]) SITE1.M14(VDD_PCIE[6]) SITE1.M16(VDD_PCIE[7]) SITE1.M18(VDD_PCIE[8]) SITE1.M20(VDD_PCIE[9]) SITE1.M22(VDD_PCIE[10]) SITE1.N15(VDD_PCIE[11]) SITE1.N17(VDD_PCIE[12])
S1_DPS20: BD15.1 BD16.1 C38.1 C39.1 C40.1 C41.1 C42.1 C43.1 C44.1 C45.1 C46.1 C47.1 C186.1 C187.1 C188.1 C189.1 C190.1 C289.1 R23.1 R24.1 S1_DPS20.1(TP) SITE1.J11(VDDH_PCIE[1]) SITE1.J21(VDDH_PCIE[2]) SITE1.K12(VDDH_PCIE[3]) SITE1.K14(VDDH_PCIE[4]) SITE1.K16(VDDH_PCIE[5]) SITE1.K18(VDDH_PCIE[6]) SITE1.K20(VDDH_PCIE[7]) SITE1.K22(VDDH_PCIE[8]) SITE1.L11(VDDH_PCIE[9]) SITE1.L21(VDDH_PCIE[10])
S1_DPS23: C48.1 C49.1 C50.1 C51.1 C52.1 C53.1 C54.1 C55.1 C56.1 C57.1 C191.1 C192.1 C193.1 C194.1 C195.1 R27.1 R28.1 R29.1 R30.1 R154.1 R163.1 S1_DPS23.1(TP) SITE1.AA7(VDDQ_0[1]) SITE1.AC7(VDDQ_0[2]) SITE1.AE7(VDDQ_0[3]) SITE1.G7(VDDQ_0[4]) SITE1.J7(VDDQ_0[5]) SITE1.L7(VDDQ_0[6]) SITE1.N7(VDDQ_0[7]) SITE1.R7(VDDQ_0[8]) SITE1.U7(VDDQ_0[9]) SITE1.W7(VDDQ_0[10])
S1_DPS27: C15.1 C16.1 C17.1 C18.1 C19.1 C20.1 C21.1 C22.1 C23.1 C24.1 C25.1 C196.1 C197.1 C198.1 C199.1 C200.1 R33.1 R34.1 R36.1 R155.1 R164.1 S1_DPS27.1(TP) SITE1.AB26(VDDQ_1[1]) SITE1.AD26(VDDQ_1[2]) SITE1.AF26(VDDQ_1[3]) SITE1.F26(VDDQ_1[4]) SITE1.H26(VDDQ_1[5]) SITE1.K26(VDDQ_1[6]) SITE1.M26(VDDQ_1[7]) SITE1.P26(VDDQ_1[8]) SITE1.T26(VDDQ_1[9]) SITE1.V26(VDDQ_1[10]) SITE1.Y26(VDDQ_1[11])
S1_DPS31: C137.1 C211.1 C212.1 C213.1 C214.1 C215.1 K8.4 K8.5 R51.1 R52.1 R54.1 S1_DPS31.1(TP)
S1_DPS33: C138.1 C139.1 C140.1 C141.1 C142.1 C143.1 C144.1 C145.1 C146.1 C147.1 C148.1 C149.1 C150.1 C151.1 C152.1 C153.1 C154.1 C155.1 C156.1 C157.1 C158.1 C159.1 C160.1 C161.1 C162.1 C163.1 C164.1 C165.1 C166.1 C167.1 C168.1 C169.1 C170.1 C171.1 C172.1 C173.1 C174.1 C175.1 C176.1 C177.1 C178.1 C179.1 C180.1 C419.1 C420.1 C421.1 C422.1 C423.1 C424.1 C425.1 C426.1 C427.1 C428.1 C429.1 C430.1 C431.1 C432.1 C433.1 C434.1 C435.1 C436.1 C437.1 C438.1 C439.1 C440.1 C441.1 C442.1 C443.1 C444.1 C445.1 C446.1 C447.1 C448.1 C449.1 C450.1 C451.1 C452.1 C453.1 C454.1 C455.1 C456.1 C457.1 C458.1 C459.1 C460.1 R218.1 R219.1 R220.1 R221.1 R222.1 R223.1 R224.1 R225.1 R226.1 R227.1 R228.1 R230.1 R231.1 R232.1 R233.1 S1_DPS33.1(TP) SITE1.AA13(VDD[1]) SITE1.AA15(VDD[2]) SITE1.AA17(VDD[3]) SITE1.AA19(VDD[4]) SITE1.AB14(VDD[5]) SITE1.AB16(VDD[6]) SITE1.AB18(VDD[7]) SITE1.AB20(VDD[8]) SITE1.AC13(VDD[9]) SITE1.AC15(VDD[10]) SITE1.AC17(VDD[11]) SITE1.AC19(VDD[12]) SITE1.AD14(VDD[13]) SITE1.AD16(VDD[14]) SITE1.AD18(VDD[15]) SITE1.AD20(VDD[16]) SITE1.N13(VDD[17]) SITE1.N19(VDD[18]) SITE1.P14(VDD[19]) SITE1.P16(VDD[20]) SITE1.P18(VDD[21]) SITE1.P20(VDD[22]) SITE1.R15(VDD[23]) SITE1.R17(VDD[24]) SITE1.R19(VDD[25]) SITE1.T14(VDD[26]) SITE1.T16(VDD[27]) SITE1.T18(VDD[28]) SITE1.T20(VDD[29]) SITE1.U13(VDD[30]) SITE1.U15(VDD[31]) SITE1.U19(VDD[32]) SITE1.V14(VDD[33]) SITE1.V18(VDD[34]) SITE1.V20(VDD[35]) SITE1.W13(VDD[36]) SITE1.W15(VDD[37]) SITE1.W17(VDD[38]) SITE1.W19(VDD[39]) SITE1.Y14(VDD[40]) SITE1.Y16(VDD[41]) SITE1.Y18(VDD[42]) SITE1.Y20(VDD[43])
S1_DPS49: C85.1 C86.1 C87.1 C88.1 C89.1 C90.1 C91.1 C92.1 C93.1 C94.1 C95.1 C96.1 C97.1 C98.1 C99.1 C100.1 C101.1 C102.1 C103.1 C104.1 C105.1 C106.1 C107.1 C108.1 C109.1 C110.1 C332.1 C333.1 C334.1 C335.1 C336.1 C337.1 C338.1 C339.1 C340.1 C341.1 C342.1 C343.1 C344.1 C345.1 C346.1 C347.1 C348.1 C349.1 C350.1 C351.1 C352.1 C353.1 C354.1 C355.1 C356.1 C357.1 C358.1 C359.1 C360.1 C361.1 C362.1 C363.1 C364.1 C365.1 C366.1 C367.1 C368.1 C369.1 C370.1 C371.1 C372.1 C373.1 R75.1 R76.1 R77.1 R78.1 R79.1 R80.1 R156.1 R157.1 R158.1 R165.1 R166.1 R167.1 R168.1 R169.1 R170.1 S1_DPS49.1(TP) SITE1.AA9(VDD_DDR_PHY_0[1]) SITE1.AB8(VDD_DDR_PHY_0[3]) SITE1.AB10(VDD_DDR_PHY_0[2]) SITE1.AC9(VDD_DDR_PHY_0[4]) SITE1.AD8(VDD_DDR_PHY_0[6]) SITE1.AD10(VDD_DDR_PHY_0[5]) SITE1.AE9(VDD_DDR_PHY_0[7]) SITE1.AF10(VDD_DDR_PHY_0[8]) SITE1.G9(VDD_DDR_PHY_0[9]) SITE1.H8(VDD_DDR_PHY_0[10]) SITE1.J9(VDD_DDR_PHY_0[11]) SITE1.K8(VDD_DDR_PHY_0[12]) SITE1.L9(VDD_DDR_PHY_0[13]) SITE1.M8(VDD_DDR_PHY_0[14]) SITE1.N9(VDD_DDR_PHY_0[15]) SITE1.P8(VDD_DDR_PHY_0[17]) SITE1.P10(VDD_DDR_PHY_0[16]) SITE1.R9(VDD_DDR_PHY_0[18]) SITE1.T8(VDD_DDR_PHY_0[20]) SITE1.T10(VDD_DDR_PHY_0[19]) SITE1.U9(VDD_DDR_PHY_0[21]) SITE1.V8(VDD_DDR_PHY_0[23]) SITE1.V10(VDD_DDR_PHY_0[22]) SITE1.W9(VDD_DDR_PHY_0[24]) SITE1.Y8(VDD_DDR_PHY_0[26]) SITE1.Y10(VDD_DDR_PHY_0[25])
S1_DPS57: C111.1 C112.1 C113.1 C114.1 C115.1 C116.1 C117.1 C118.1 C119.1 C120.1 C121.1 C122.1 C123.1 C124.1 C125.1 C126.1 C127.1 C128.1 C129.1 C130.1 C131.1 C132.1 C133.1 C134.1 C135.1 C136.1 C374.1 C375.1 C376.1 C377.1 C378.1 C379.1 C380.1 C381.1 C382.1 C383.1 C384.1 C385.1 C386.1 C387.1 C388.1 C389.1 C390.1 C391.1 C392.1 C393.1 C394.1 C395.1 C396.1 C397.1 C398.1 C399.1 C400.1 C401.1 C402.1 C403.1 C404.1 C405.1 C406.1 C407.1 C408.1 C409.1 C410.1 C411.1 C412.1 C413.1 C414.1 C415.1 R198.1 R199.1 R200.1 R201.1 R202.1 R203.1 R204.1 R205.1 R206.1 R207.1 R208.1 R210.1 R211.1 R212.1 R213.1 S1_DPS57.1(TP) SITE1.AA23(VDD_DDR_PHY_1[1]) SITE1.AA25(VDD_DDR_PHY_1[2]) SITE1.AB24(VDD_DDR_PHY_1[3]) SITE1.AC23(VDD_DDR_PHY_1[4]) SITE1.AC25(VDD_DDR_PHY_1[5]) SITE1.AD24(VDD_DDR_PHY_1[6]) SITE1.AE25(VDD_DDR_PHY_1[7]) SITE1.AF24(VDD_DDR_PHY_1[8]) SITE1.G25(VDD_DDR_PHY_1[9]) SITE1.H24(VDD_DDR_PHY_1[10]) SITE1.J25(VDD_DDR_PHY_1[11]) SITE1.K24(VDD_DDR_PHY_1[12]) SITE1.L25(VDD_DDR_PHY_1[13]) SITE1.M24(VDD_DDR_PHY_1[14]) SITE1.N23(VDD_DDR_PHY_1[15]) SITE1.N25(VDD_DDR_PHY_1[16]) SITE1.P24(VDD_DDR_PHY_1[17]) SITE1.R23(VDD_DDR_PHY_1[18]) SITE1.R25(VDD_DDR_PHY_1[19]) SITE1.T24(VDD_DDR_PHY_1[20]) SITE1.U23(VDD_DDR_PHY_1[21]) SITE1.U25(VDD_DDR_PHY_1[22]) SITE1.V24(VDD_DDR_PHY_1[23]) SITE1.W23(VDD_DDR_PHY_1[24]) SITE1.W25(VDD_DDR_PHY_1[25]) SITE1.Y24(VDD_DDR_PHY_1[26])
S1_OSC4_N: R248.1 U4.5(OUTN)
S1_OSC4_P: R249.1 U4.4(OUTP)
S1_OSC4_R_N: R246.1 R248.2 U3.1(CLKIN_P)
S1_OSC4_R_P: R247.1 R249.2 U3.2(CLKIN_N)
S1_OSC5_6_GND: C470.2 C471.2 C472.2 C473.2 K15.G1 K15.G2 K15.G3 K16.G1 K16.G2 K16.G3 OSC5.3(GND) OSC6.3(GND) R259.2 R260.2 R263.2 R264.2 R265.2 R266.2 S1_OSC5_6_GND.1(TP) S1_OSC5_6_GND1.1(TP) S1_OSC5_6_GND2.1(TP) S1_OSC5_6_GND3.1(TP) S1_OSC5_6_GND4.1(TP) S1_OSC5_6_GND5.1(TP)
S1_OSC5_A_N: K15.3 R268.1
S1_OSC5_A_P: K15.7 R267.1
S1_OSC5_B_N: R256.1 R263.1 R268.2
S1_OSC5_B_P: R255.1 R264.1 R267.2
S1_OSC5_C_N: OSC5.5(OUTN) R256.2
S1_OSC5_C_P: OSC5.4(OUTP) R255.2
S1_OSC5_N: K15.2 S1_OSC5_N.1(TP)
S1_OSC5_P: K15.8 S1_OSC5_P.1(TP)
S1_OSC6_A_N: K16.3 R269.1
S1_OSC6_A_P: K16.7 R270.1
S1_OSC6_B_N: R258.1 R265.1 R269.2
S1_OSC6_B_P: R257.1 R266.1 R270.2
S1_OSC6_C_N: OSC6.5(OUTN) R258.2
S1_OSC6_C_P: OSC6.4(OUTP) R257.2
S1_OSC6_N: K16.2 S1_OSC6_N.1(TP)
S1_OSC6_P: K16.8 S1_OSC6_P.1(TP)
S1_OSC7_8_GND: C474.2 C475.2 C476.2 C477.2 K18.G1 K18.G2 K18.G3 K20.G1 K20.G2 K20.G3 OSC7.3(GND) OSC8.3(GND) R273.2 R275.2 R276.2 R281.2 R283.2 R284.2 S1_OSC7_8_GND.1(TP) S1_OSC7_8_GND1.1(TP) S1_OSC7_8_GND2.1(TP) S1_OSC7_8_GND3.1(TP) S1_OSC7_8_GND4.1(TP) S1_OSC7_8_GND5.1(TP)
S1_OSC7_A_N: K18.3 R277.1
S1_OSC7_A_P: K18.7 R278.1
S1_OSC7_B_N: R272.1 R275.1 R277.2
S1_OSC7_B_P: R271.1 R276.1 R278.2
S1_OSC7_C_N: OSC7.5(OUTN) R272.2
S1_OSC7_C_P: OSC7.4(OUTP) R271.2
S1_OSC7_N: K18.2 S1_OSC7_N.1(TP)
S1_OSC7_P: K18.8 S1_OSC7_P.1(TP)
S1_OSC8_A_N: K20.3 R285.1
S1_OSC8_A_P: K20.7 R286.1
S1_OSC8_B_N: R279.1 R284.1 R285.2
S1_OSC8_B_P: R280.1 R283.1 R286.2
S1_OSC8_C_N: OSC8.5(OUTN) R279.2
S1_OSC8_C_P: OSC8.4(OUTP) R280.2
S1_OSC8_N: K20.2 S1_OSC8_N.1(TP)
S1_OSC8_P: K20.8 S1_OSC8_P.1(TP)
S1_PCIE_RX_N[0]: C252.1 R117.1 SITE1.A24(PCIE_RX_N[0])
S1_PCIE_RX_N[1]: C256.1 R125.1 SITE1.A22(PCIE_RX_N[1])
S1_PCIE_RX_N[2]: C261.1 R129.1 SITE1.A20(PCIE_RX_N[2])
S1_PCIE_RX_N[3]: C265.1 R133.1 SITE1.A18(PCIE_RX_N[3])
S1_PCIE_RX_N[4]: C269.1 R137.1 SITE1.A16(PCIE_RX_N[4])
S1_PCIE_RX_N[5]: C273.1 R142.1 SITE1.A14(PCIE_RX_N[5])
S1_PCIE_RX_N[6]: C277.1 R146.1 SITE1.A12(PCIE_RX_N[6])
S1_PCIE_RX_N[7]: C281.1 R150.1 SITE1.A10(PCIE_RX_N[7])
S1_PCIE_RX_P[0]: C253.1 R118.1 SITE1.B24(PCIE_RX_P[0])
S1_PCIE_RX_P[1]: C257.1 R126.1 SITE1.B22(PCIE_RX_P[1])
S1_PCIE_RX_P[2]: C260.1 R130.1 SITE1.B20(PCIE_RX_P[2])
S1_PCIE_RX_P[3]: C264.1 R134.1 SITE1.B18(PCIE_RX_P[3])
S1_PCIE_RX_P[4]: C268.1 R138.1 SITE1.B16(PCIE_RX_P[4])
S1_PCIE_RX_P[5]: C272.1 R141.1 SITE1.B14(PCIE_RX_P[5])
S1_PCIE_RX_P[6]: C276.1 R145.1 SITE1.B12(PCIE_RX_P[6])
S1_PCIE_RX_P[7]: C280.1 R149.1 SITE1.B10(PCIE_RX_P[7])
S1_PCIE_TX_1_N[0]: C254.1 S1_PCIE_TX_N[0].1
S1_PCIE_TX_1_N[1]: C258.1 S1_PCIE_TX_N[1].1
S1_PCIE_TX_1_N[2]: C262.1 S1_PCIE_TX_N[2].1
S1_PCIE_TX_1_N[3]: C266.1 S1_PCIE_TX_N[3].1
S1_PCIE_TX_1_N[4]: C270.1 S1_PCIE_TX_N[4].1
S1_PCIE_TX_1_N[5]: C274.1 S1_PCIE_TX_N[5].1
S1_PCIE_TX_1_N[6]: C278.1 S1_PCIE_TX_N[6].1
S1_PCIE_TX_1_N[7]: C282.1 S1_PCIE_TX_N[7].1
S1_PCIE_TX_1_P[0]: C255.1 S1_PCIE_TX_P[0].1
S1_PCIE_TX_1_P[1]: C259.1 S1_PCIE_TX_P[1].1
S1_PCIE_TX_1_P[2]: C263.1 S1_PCIE_TX_P[2].1
S1_PCIE_TX_1_P[3]: C267.1 S1_PCIE_TX_P[3].1
S1_PCIE_TX_1_P[4]: C271.1 S1_PCIE_TX_P[4].1
S1_PCIE_TX_1_P[5]: C275.1 S1_PCIE_TX_P[5].1
S1_PCIE_TX_1_P[6]: C279.1 S1_PCIE_TX_P[6].1
S1_PCIE_TX_1_P[7]: C283.1 S1_PCIE_TX_P[7].1
S1_PCIE_TX_N[0]: C252.2 C254.2 R123.1 SITE1.D23(PCIE_TX_N[0])
S1_PCIE_TX_N[1]: C256.2 C258.2 R127.1 SITE1.D21(PCIE_TX_N[1])
S1_PCIE_TX_N[2]: C261.2 C262.2 R131.1 SITE1.D19(PCIE_TX_N[2])
S1_PCIE_TX_N[3]: C265.2 C266.2 R135.1 SITE1.D17(PCIE_TX_N[3])
S1_PCIE_TX_N[4]: C269.2 C270.2 R139.1 SITE1.D15(PCIE_TX_N[4])
S1_PCIE_TX_N[5]: C273.2 C274.2 R143.1 SITE1.D13(PCIE_TX_N[5])
S1_PCIE_TX_N[6]: C277.2 C278.2 R147.1 SITE1.D11(PCIE_TX_N[6])
S1_PCIE_TX_N[7]: C281.2 C282.2 R151.1 SITE1.D9(PCIE_TX_N[7])
S1_PCIE_TX_P[0]: C253.2 C255.2 R124.1 SITE1.E23(PCIE_TX_P[0])
S1_PCIE_TX_P[1]: C257.2 C259.2 R128.1 SITE1.E21(PCIE_TX_P[1])
S1_PCIE_TX_P[2]: C260.2 C263.2 R132.1 SITE1.E19(PCIE_TX_P[2])
S1_PCIE_TX_P[3]: C264.2 C267.2 R136.1 SITE1.E17(PCIE_TX_P[3])
S1_PCIE_TX_P[4]: C268.2 C271.2 R140.1 SITE1.E15(PCIE_TX_P[4])
S1_PCIE_TX_P[5]: C272.2 C275.2 R144.1 SITE1.E13(PCIE_TX_P[5])
S1_PCIE_TX_P[6]: C276.2 C279.2 R148.1 SITE1.E11(PCIE_TX_P[6])
S1_PCIE_TX_P[7]: C280.2 C283.2 R152.1 SITE1.E9(PCIE_TX_P[7])
S1_PHY0_RESEXT: R108.1 R109.1 SITE1.H17(PHY0_RESEXT)
S1_PHY0_RESEXT_1: K3.3 R109.2
S1_PHY0_SYS_CLK1_N: K1.3 R241.1 R242.1
S1_PHY0_SYS_CLK1_P: K1.7 R240.1 R243.1
S1_PHY0_SYS_CLK1R_N: R242.2 U3.10(CLK2_N)
S1_PHY0_SYS_CLK1R_P: R243.2 U3.9(CLK2_P)
S1_PHY0_SYS_CLK2_N: R100.2 U1.5(OUTN)
S1_PHY0_SYS_CLK2_P: R101.2 U1.4(OUTP)
S1_PHY0_SYS_CLK3_N: R100.1 R119.1 R241.2
S1_PHY0_SYS_CLK3_P: R101.1 R120.1 R240.2
S1_PHY0_SYS_CLK_N: K1.2 SITE1.G19(PHY0_SYS_CLK_N)
S1_PHY0_SYS_CLK_P: K1.8 SITE1.H19(PHY0_SYS_CLK_P)
S1_PHY1_RESEXT: R110.1 R111.1 SITE1.H13(PHY1_RESEXT)
S1_PHY1_RESEXT_1: K4.3 R111.2
S1_PHY1_SYS_CLK1_N: K2.3 R239.1 R245.2
S1_PHY1_SYS_CLK1_P: K2.7 R238.1 R244.2
S1_PHY1_SYS_CLK1R_N: R245.1 U3.17(CLK1_N)
S1_PHY1_SYS_CLK1R_P: R244.1 U3.16(CLK1_P)
S1_PHY1_SYS_CLK2_N: R102.2 U2.5(OUTN)
S1_PHY1_SYS_CLK2_P: R103.2 U2.4(OUTP)
S1_PHY1_SYS_CLK3_N: R102.1 R121.1 R239.2
S1_PHY1_SYS_CLK3_P: R103.1 R122.1 R238.2
S1_PHY1_SYS_CLK_N: K2.2 SITE1.G15(PHY1_SYS_CLK_N)
S1_PHY1_SYS_CLK_P: K2.8 SITE1.H15(PHY1_SYS_CLK_P)
S1_UHC4_1F: R80.2 R165.2 R166.2 R167.2
S1_UHC4_1GS: R81.2
S1_UHC4_1S: R79.2
S1_UHC4_2F: R201.2 R202.2 R203.2 R208.2
S1_UHC4_2GS: R209.2
S1_UHC4_2S: R207.2
S1_UHC4_3F: R221.2 R222.2 R223.2 R228.2
S1_UHC4_3GS: R229.2
S1_UHC4_3S: R227.2
S1_VCC18V_VQPS: K8.3 K8.6 SITE1.AE21(VCC18V_VQPS)
S1_XIN: K7.3 SITE1.AL16(XIN)
UDBGND: BD1.2 BD2.2 BD3.2 BD4.2 BD5.2 BD6.2 BD7.2 BD8.2 BD9.2 BD10.2 BD11.2 BD12.2 CB1.2 CB2.2 CB3.2 CB4.2 CB5.2 CB6.2 CB7.2 CB8.2 CB9.2 CB10.2 CB15.2 CB16.2 LDB5.2(B) UB1.1(NC) UB1.2(A1/NC) UB1.3(A2) UB1.4(GND) UB1.7(WP) UHC230.B2(GND2) UHC230.D2(GND1) UHC430.B2(GND2) UHC430.D2(GND1) UTL1.A02 UTL1.A08 UTL1.A10 UTL1.A12 UTL1.A14 UTL1.B01 UTL1.B07 UTL1.B09 UTL1.B11 UTL1.B13 UTL2.A02 UTL2.A08 UTL2.A10 UTL2.A12 UTL2.A14 UTL2.B01 UTL2.B07 UTL2.B09 UTL2.B11 UTL2.B13 UTL3.A02 UTL3.A08 UTL3.A10 UTL3.A12 UTL3.A14 UTL3.B01 UTL3.B07 UTL3.B09 UTL3.B11 UTL3.B13 UTL4.A02 UTL4.A08 UTL4.A10 UTL4.A12 UTL4.A14 UTL4.B01 UTL4.B07 UTL4.B09 UTL4.B11 UTL4.B13 UTL5.A02 UTL5.A08 UTL5.A10 UTL5.A12 UTL5.A14 UTL5.B01 UTL5.B07 UTL5.B09 UTL5.B11 UTL5.B13 UTL8.A02 UTL8.A08 UTL8.A10 UTL8.A12 UTL8.A14 UTL8.B01 UTL8.B07 UTL8.B09 UTL8.B11 UTL8.B13 XC1.1
UHC230A_CMON3: UHC230.C2(CMON3)
UHC230A_CMON4: UHC230.A2(CMON4)
UHC230A_DS3+: UHC230.B1(+DS3)
UHC230A_DS3-: UHC230.A1(-DS3)
UHC230A_DS4+: UHC230.B3(+DS4)
UHC230A_DS4-: UHC230.A3(-DS4)
UHC230A_DUT_CAP_ON_3: UHC230.D4(DUT_CAP_ON_3)
UHC230A_DUT_CAP_ON_4: UHC230.A4(DUT_CAP_ON_4)
UHC230A_GANG_OUT: UHC230.B4(GANG_OUT)
UHC230A_GS3: UHC230.C1(GS3)
UHC230A_GS4: UHC230.C3(GS4)
UHC230A_P3: UHC230.P3 UHC230.P3_1 UHC230.P3_2 UHC230.P3_3 UHC230.P3_4 UHC230.P3_5 UHC230.P3_6 UHC230.P3_7 UHC230.P3_8 UHC230.P3_9 UHC230.P3_10 UHC230.P3_11 UHC230.P3_12 UHC230.P3_13 UHC230.P3_14 UHC230.P3_15 UHC230.P3_16 UHC230.P3_17 UHC230.P3_18
UHC230A_P4: UHC230.P4 UHC230.P4_1 UHC230.P4_2 UHC230.P4_3 UHC230.P4_4 UHC230.P4_5 UHC230.P4_6 UHC230.P4_7 UHC230.P4_8 UHC230.P4_9 UHC230.P4_10 UHC230.P4_11 UHC230.P4_12 UHC230.P4_13 UHC230.P4_14 UHC230.P4_15 UHC230.P4_16 UHC230.P4_17 UHC230.P4_18
UHC230A_PS3: UHC230.D1(PS3)
UHC230A_PS4: UHC230.D3(PS4)
UHC230A_SAFETY_LINE: UHC230.C4(SAFETY_LINE)
UHC430B_CMON1: UHC430.C2(CMON1)
UHC430B_CMON2: UHC430.A2(CMON2)
UHC430B_DS1+: UHC430.B1(+DS1)
UHC430B_DS1-: UHC430.A1(-DS1)
UHC430B_DS2+: UHC430.B3(+DS2)
UHC430B_DS2-: UHC430.A3(-DS2)
UHC430B_DUT_CAP_ON_1: UHC430.D4(DUT_CAP_ON_1)
UHC430B_DUT_CAP_ON_2: UHC430.A4(DUT_CAP_ON_2)
UHC430B_GANG_IN: UHC430.B4(GANG_IN)
UHC430B_GS1: UHC430.C1(GS1)
UHC430B_GS2: UHC430.C3(GS2)
UHC430B_P1: UHC430.P1 UHC430.P1_1 UHC430.P1_2 UHC430.P1_3 UHC430.P1_4 UHC430.P1_5 UHC430.P1_6 UHC430.P1_7 UHC430.P1_8 UHC430.P1_9 UHC430.P1_10 UHC430.P1_11 UHC430.P1_12 UHC430.P1_13 UHC430.P1_14 UHC430.P1_15 UHC430.P1_16 UHC430.P1_17 UHC430.P1_18
UHC430B_P2: UHC430.P2 UHC430.P2_1 UHC430.P2_2 UHC430.P2_3 UHC430.P2_4 UHC430.P2_5 UHC430.P2_6 UHC430.P2_7 UHC430.P2_8 UHC430.P2_9 UHC430.P2_10 UHC430.P2_11 UHC430.P2_12 UHC430.P2_13 UHC430.P2_14 UHC430.P2_15 UHC430.P2_16 UHC430.P2_17 UHC430.P2_18
UHC430B_PS1: UHC430.D1(PS1)
UHC430B_PS2: UHC430.D3(PS2)
UT1_PDCF: UTL1.B15
UT1_PDCS: UTL1.A15
UT1_PGDS: UTL1.A16
UT1_PGRD: UTL1.B16
UT1_UP5V: CB1.1 CB2.1 CB3.1 CB4.1 CB5.1 CB6.1 CB7.1 CB8.1 K1.1(V+) K2.1(V+) K3.1(V+) K4.1(V+) K5.1(V+) K6.1(V+) K7.1(V+) K8.1(V+) K9.1(V+) K10.1(V+) K11.1(V+) K12.1(V+) KS1.1(V+) KS2.1(V+) KS3.3(V+) KS4.3(V+) LRB1.1 LRB2.1 LRB3.1 LRB4.1 LRB5.2 RB1.1 RB2.1 RV2.1 RV3.1 RV4.1 RV5.1 RV6.1 RV7.1 RV8.1 RV9.1 RV10.1 RV11.1 RV12.1 RV13.1 UB1.8(VCC) UHC430.C4(+5V) UT_UP5V.1(TP) UTL1.A05 UTL1.B04 UTL2.A05 UTL2.B04 UTL3.A05 UTL3.B04 UTL4.A05 UTL4.B04 XC1.2
UT1_URW00: KS3.1(V-) LDB3.2(B) UTL1.A01
UT1_URW01: KS4.1(V-) LDB4.2(B) UTL1.B02
UT1_URW02: KS2.9(V-) LDB2.2(B) UTL1.A03
UT1_URW03: KS1.9(V-) LDB1.2(B) UTL1.B03
UT1_URW04: UTL1.A04
UT1_URW05: UTL1.B05
UT1_URW06: UTL1.A06
UT1_UW07: UTL1.B06
UT1_UW08: UTL1.A07
UT1_UW09: UTL1.B08
UT1_UW10: UTL1.A09
UT1_UW11: UTL1.B10
UT1_UW12: UTL1.A11
UT1_UW13: UTL1.B12
UT1_UW14: RB1.2 UB1.6(SCL) UTL1.A13
UT1_UW15: RB2.2 UB1.5(SDA) UTL1.B14
UT2_PDCF: UTL2.B15
UT2_PDCS: UTL2.A15
UT2_PGDS: UTL2.A16
UT2_PGRD: UTL2.B16
UT2_URW00: UTL2.A01
UT2_URW01: UTL2.B02
UT2_URW02: UTL2.A03
UT2_URW03: UTL2.B03
UT2_URW04: UTL2.A04
UT2_URW05: UTL2.B05
UT2_URW06: UTL2.A06
UT2_UW07: UTL2.B06
UT2_UW08: UTL2.A07
UT2_UW09: UTL2.B08
UT2_UW10: UTL2.A09
UT2_UW11: UTL2.B10
UT2_UW12: UTL2.A11
UT2_UW13: UTL2.B12
UT2_UW14: UTL2.A13
UT2_UW15: UTL2.B14
UT3_PDCF: UTL3.B15
UT3_PDCS: UTL3.A15
UT3_PGDS: UTL3.A16
UT3_PGRD: UTL3.B16
UT3_URW00: UTL3.A01
UT3_URW01: UTL3.B02
UT3_URW02: UTL3.A03
UT3_URW03: UTL3.B03
UT3_URW04: UTL3.A04
UT3_URW05: UTL3.B05
UT3_URW06: UTL3.A06
UT3_UW07: UTL3.B06
UT3_UW08: UTL3.A07
UT3_UW09: UTL3.B08
UT3_UW10: UTL3.A09
UT3_UW11: UTL3.B10
UT3_UW12: UTL3.A11
UT3_UW13: UTL3.B12
UT3_UW14: UTL3.A13
UT3_UW15: UTL3.B14
UT4_PDCF: UTL4.B15
UT4_PDCS: UTL4.A15
UT4_PGDS: UTL4.A16
UT4_PGRD: UTL4.B16
UT4_URW00: UTL4.A01
UT4_URW01: UTL4.B02
UT4_URW02: UTL4.A03
UT4_URW03: UTL4.B03
UT4_URW04: UTL4.A04
UT4_URW05: UTL4.B05
UT4_URW06: UTL4.A06
UT4_UW07: UTL4.B06
UT4_UW08: UTL4.A07
UT4_UW09: UTL4.B08
UT4_UW10: UTL4.A09
UT4_UW11: UTL4.B10
UT4_UW12: UTL4.A11
UT4_UW13: UTL4.B12
UT4_UW14: UTL4.A13
UT4_UW15: UTL4.B14
UT5_PDCF: UTL5.B15
UT5_PDCS: UTL5.A15
UT5_PGDS: UTL5.A16
UT5_PGRD: UTL5.B16
UT5_UP5V: CB9.1 CB10.1 UTL5.A05 UTL5.B04
UT5_UW00: UTL5.A01
UT5_UW01: UTL5.B02
UT5_UW02: UTL5.A03
UT5_UW03: UTL5.B03
UT5_UW04: UTL5.A04
UT5_UW05: UTL5.B05
UT5_UW06: UTL5.A06
UT5_UW07: UTL5.B06
UT5_UW08: UTL5.A07
UT5_UW09: UTL5.B08
UT5_UW10: UTL5.A09
UT5_UW11: UTL5.B10
UT5_UW12: UTL5.A11
UT5_UW13: UTL5.B12
UT5_UW14: UTL5.A13
UT5_UW15: UTL5.B14
UT8_PDCF: UTL8.B15
UT8_PDCS: UTL8.A15
UT8_PGDS: UTL8.A16
UT8_PGRD: UTL8.B16
UT8_UP5V: CB15.1 CB16.1 UTL8.A05 UTL8.B04
UT8_UW00: UTL8.A01
UT8_UW01: UTL8.B02
UT8_UW02: UTL8.A03
UT8_UW03: UTL8.B03
UT8_UW04: UTL8.A04
UT8_UW05: UTL8.B05
UT8_UW06: UTL8.A06
UT8_UW07: UTL8.B06
UT8_UW08: UTL8.A07
UT8_UW09: UTL8.B08
UT8_UW10: UTL8.A09
UT8_UW11: UTL8.B10
UT8_UW12: UTL8.A11
UT8_UW13: UTL8.B12
UT8_UW14: UTL8.A13
UT8_UW15: UTL8.B14
N19435169: BD13.2 BD14.2 C285.1 C287.1 R15.1 R16.1 R153.1 R162.1
N19572213: DV2.1(A) RV2.2
N19572313: DV3.1(A) RV3.2
N19572428: K10.6 R104.1 U1.1(OE/NF)
N19572509: K11.6 R106.1 U2.1(OE/NF)
N19574075: DV4.1(A) RV4.2
N19574343: DV5.1(A) RV5.2
N19575291: DV8.1(A) RV8.2
N19575453: K7.4 OSC1.3(OUTPUT)
N19585514: DV10.1(A) RV10.2
N19585599: K9.3 K9.6 OSC1.1(EN)
N19585804: K9.4 R116.1
N19747460: BD16.2 R21.1
N19747478: BD15.2 C288.1 C290.1 R22.1
N19756616: DV11.1(A) RV11.2
N19756896: K10.4 R214.1
N19756906: K10.5 R214.2
N19757084: DV12.1(A) RV12.2
N19757142: K11.4 R215.1
N19757144: K11.5 R215.2
N19788638: DV9.1(A) RV9.2
N20007134: DV6.1(A) RV6.2
N20007610: DV7.1(A) RV7.2
N20116208: BD18.2 C462.1 C463.1 C464.1 C465.1 C466.1 R234.1 U3.3(VDDCLK[5]) U3.8(VDDCLK[4]) U3.14(VDDCLK[1]) U3.18(VDDCLK[2]) U3.19(VDDCLK[3])
N20116223: C461.1 R234.2 U3.6(VDDA)
N20117866: K12.6 R235.1 U4.1(OE/NF)
N20117958: DV13.1(A) RV13.2
N20118012: K12.4 R236.1
N20118014: K12.5 R236.2
N20118228: R252.1 R254.1 U3.13(LOS#)
N20118429: R253.1 U3.11(ZOUT_SEL)
N20125555: R250.1 U3.12(OE2#)
N20125558: R251.1 U3.15(OE1#)
N20322895: KS2.4 KS2-4.1(TP)
N20322897: LDB1.1(A) LRB1.2
N20322901: KS2.3 KS2-3.1(TP)
N20322902: KS2.6 KS2-6.1(TP)
N20322905: KS2.7 KS2-7.1(TP)
N20322907: LDB2.1(A) LRB2.2
N20322911: KS1.4 KS1-4.1(TP)
N20322913: KS1.3 KS1-3.1(TP)
N20322914: KS1.6 KS1-6.1(TP)
N20322915: KS1.7 KS1-7.1(TP)
N20322919: KS1.2 KS1-2.1(TP)
N20322920: KS1.8 KS1-8.1(TP)
N20322921: KS2.2 KS2-2.1(TP)
N20322922: KS2.8 KS2-8.1(TP)
N20322925: LDB3.1(A) LRB3.2
N20322930: LDB4.1(A) LRB4.2
N20322942: KS4.4 KS4-4.1(TP)
N20322943: KS4.5 KS4-5.1(TP)
N20322944: KS4.8 KS4-8.1(TP)
N20322953: KS3.8 KS3-8.1(TP)
N20322954: KS3.4 KS3-4.1(TP)
N20322955: KS3.5 KS3-5.1(TP)
N20322961: LDB5.1(A) LRB5.1
N20403651: BD19.2 BD20.2 C470.1 C472.1 K13.3 OSC5.6(VDD)
N20403655: K13.6 OSC5.1(OE/NF) R259.1
N20403856: DV14.2(B) K13.8(V-) S1_K13_CBIT.1(TP)
N20403862: DV14.1(A) RV14.2
N20403864: K13.1(V+) K15.1(V+) RV14.1 RV16.1 S1_OSC5_RLY_5V.1(TP)
N20403912: K13.4 R261.1
N20403914: K13.5 R261.2
N20408352: DV16.2(B) K15.9(V-) S1_K15_CBIT.1(TP)
N20408383: DV16.1(A) RV16.2
N20409909: BD21.2 BD22.2 C471.1 C473.1 K14.3 OSC6.6(VDD)
N20409913: K14.6 OSC6.1(OE/NF) R260.1
N20410006: DV15.2(B) K14.8(V-) S1_K14_CBIT.1(TP)
N20410012: DV15.1(A) RV15.2
N20410014: K14.1(V+) K16.1(V+) RV15.1 RV17.1 S1_OSC6_RLY_5V.1(TP)
N20410038: K14.4 R262.1
N20410040: K14.5 R262.2
N20410345: BD19.1 BD20.1 S1_DB_OSC5_PWR.1(TP)
N20410600: DV17.2(B) K16.9(V-) S1_K16_CBIT.1(TP)
N20410614: DV17.1(A) RV17.2
N20412222: BD21.1 BD22.1 S1_DB_OSC6_PWR.1(TP)
N20412556: K15.6 S1_K15_6.1(TP)
N20412563: K15.4 S1_K15_4.1(TP)
N20412610: K16.6 S1_K16_6.1(TP)
N20412613: K16.4 S1_K16_4.1(TP)
N20439603: BD23.2 BD24.2 C474.1 C475.1 K17.3 OSC7.6(VDD)
N20439607: K17.6 OSC7.1(OE/NF) R273.1
N20439693: DV18.2(B) K17.8(V-) S1_K17_CBIT.1(TP)
N20439699: DV18.1(A) RV18.2
N20439701: K17.1(V+) K18.1(V+) RV18.1 RV19.1 S1_OSC7_RLY_5V.1(TP)
N20439733: K17.4 R274.1
N20439735: K17.5 R274.2
N20439828: DV19.2(B) K18.9(V-) S1_K18_CBIT1.1(TP)
N20439842: DV19.1(A) RV19.2
N20439950: BD25.2 BD26.2 C476.1 C477.1 K19.3 OSC8.6(VDD)
N20439954: K19.6 OSC8.1(OE/NF) R281.1
N20440050: DV20.2(B) K19.8(V-) S1_K19_CBIT.1(TP)
N20440056: DV20.1(A) RV20.2
N20440058: K19.1(V+) K20.1(V+) RV20.1 RV21.1 S1_OSC8_RLY_5V.1(TP)
N20440074: K19.4 R282.1
N20440076: K19.5 R282.2
N20440163: BD23.1 BD24.1 S1_DB_OSC7_PWR.1(TP)
N20440184: DV21.2(B) K20.9(V-) S1_K20_CBIT.1(TP)
N20440198: DV21.1(A) RV21.2
N20440326: BD25.1 BD26.1 S1_DB_OSC8_PWR.1(TP)
N20440363: K18.6 S1_K18_6.1(TP)
N20440379: K18.4 S1_K18_4.1(TP)
N20440395: K20.6 S1_K20_6.1(TP)
N20440397: K20.4 S1_K20_4.1(TP)

Pads without a net: CSDPS225 A17 B17 C17 D17; CSDPS226 A17 D17; CSDPS229 A17 B17 C17 D17; CSDPS425 A17 B17 C17 D17; CSDPS426 A17 D17; CSDPS429 A17 B17 C17 D17; D101 17 A17 B17; D102 17 A17 B17; D103 17 A17 B17; D104 17 A17 B17; D105 17 A17 B17; D106 17 A17 B17; D107 17 A17 B17; D108 17 A17 B17; D109 17 A17 B17; D110 17 A17 B17; D111 17 A17 B17; D112 17 A17 B17; D113 17 A17 B17; D114 17 A17 B17; D115 17 A17 B17; D116 17 A17 B17; D117 17 A17 B17; D118 17 A17 B17; D119 17 A17 B17; D120 17 A17 B17; D121 17 A17 B17; D122 17 A17 B17; D123 17 A17 B17; D124 17 A17 B17; D125 17 A17 B17; D126 17 A17 B17; D127 17 A17 B17; D128 17 A17 B17; D129 17 A17 B17; D130 17 A17 B17; D131 17 A17 B17; D132 17 A17 B17; D217 17 A17 B17; D218 17 A17 B17; D219 17 A17 B17; D220 17 A17 B17; D221 17 A17 B17; D222 17 A17 B17; D223 17 A17 B17; D224 17 A17 B17; D227 01 02 03 05 06 07 08 09 10 11 12 13 14 15 16 17; D228 01 02 03 05 06 07 08 09 10 11 12 13 14 15 16 17; D301 17 A17 B17; D302 17 A17 B17; D303 17 A17 B17; D304 17 A17 B17; D305 17 A17 B17; D306 17 A17 B17; D307 17 A17 B17; D308 17 A17 B17; D309 17 A17 B17; D310 17 A17 B17; D311 17 A17 B17; D312 17 A17 B17; D313 17 A17 B17; D314 17 A17 B17; D315 17 A17 B17; D316 17 A17 B17; D317 17 A17 B17; D318 17 A17 B17; D319 17 A17 B17; D320 17 A17 B17; D321 17 A17 B17; D322 17 A17 B17; D323 17 A17 B17; D427 01 02 03 04 05 06 07 08 09 10 11 12 13 14 15 16 17; D428 01 02 03 04 05 06 07 08 09 10 11 12 13 14 15 16 17; DPS1 A04 A08 A10 A14 B04 B08 B10 B14 C04 C08 C10 C14; DPS2 A04 A08 A10 A14 B04 B08 B10 B14 C04 C08 C10 C14; DPS3 A04 A08 A10 A14 B04 B08 B10 B14 C04 C08 C10 C14; DPS4 A04 A08 A10 A14 B04 B08 B10 B14 C04 C08 C10 C14; DPS7 A04 A08 A10 A14 B04 B08 B10 B14 C04 C08 C10 C14; DPS8 A04 A08 A10 A14 B04 B08 B10 B14 C04 C08 C10 C14; FD1 1; FD2 1; FD3 1; FD4 1; FD5 1; FD6 1; FD7 1; FD8 1; FD9 1; FD10 1; FD11 1; FD12 1; FD13 1; FD14 1; FD15 1; FD16 1; FSH0AS148AA 1; K3 2 5 6 7; K4 2 5 6 7; K5 2 5 6 7; K6 2 5 6 7; K7 5 6 7; K9 5 7; K10 2 7; K11 2 7; K12 2 7; K13 2 7; K14 2 7; K17 2 7; K19 2 7; KS3 2; KS4 2; LOGO1 1; LOGO2 1; M1 1; OSC5 2; OSC6 2; OSC7 2; OSC8 2; PBGA23X23-M22X22-1-456 1; S* 1; S*#2 1; SCREW1 NUT1 NUT2 NUT3 NUT4; SITE1 NUT1 NUT2 NUT3 NUT4; U1 2; U2 2; U3 4 5; U4 2; UNK038FY- 1; UNK980FY- 1; UTL1 A17 B17; UTL2 A17 B17; UTL3 A17 B17; UTL4 A17 B17; UTL5 A17 B17; UTL8 A17 B17; WW-72178760 1

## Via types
v1: diameter 0.508, hole 0.254, TOP to BOTTOM, 2025 vias
v2: diameter 0.61, hole 0.305, TOP to BOTTOM, 84 vias
v3: diameter 0.457, hole 0.203, TOP to BOTTOM, 1850 vias
v4: diameter 0.254, hole 0.508, TOP to BOTTOM, 1 via

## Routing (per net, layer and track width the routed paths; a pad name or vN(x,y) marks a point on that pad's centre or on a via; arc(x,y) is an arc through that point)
DGND: length 151.2
  BOTTOM w0.117: S1_PCIE_TX_N[2].2 316.23,281.59 arc(315.93,280.09) v3(315.09,278.83) ; S1_PCIE_TX_P[3].4 295.91,274.47 arc(296.05,275.18) v3(296.45,275.78) ; S1_PCIE_TX_N[0].4 341.63,274.47 arc(341.77,275.18) v3(342.17,275.78) ; S1_PCIE_TX_P[4].4 280.67,274.47 arc(280.81,275.18) v3(281.21,275.78) ; S1_PCIE_TX_N[6].2 255.27,281.59 arc(254.97,280.09) v3(254.13,278.83) ; S1_PCIE_TX_P[6].4 250.19,274.47 arc(250.33,275.18) v3(250.73,275.78) ; S1_PCIE_TX_P[4].5 285.75,273.02 arc(285.45,274.51) v3(284.61,275.78) ; S1_PCIE_TX_P[2].4 311.15,274.47 arc(311.29,275.18) v3(311.69,275.78) ; S1_PCIE_TX_P[1].2 331.47,281.59 arc(331.17,280.09) v3(330.33,278.83) ; S1_PCIE_TX_P[0].3 341.63,280.14 arc(341.77,279.43) v3(342.17,278.83) ; S1_PCIE_TX_P[2].5 316.23,273.02 arc(315.93,274.51) v3(315.09,275.78) ; S1_PCIE_TX_N[2].3 311.15,280.14 arc(311.29,279.43) v3(311.69,278.83) ; S1_PCIE_TX_N[3].3 295.91,280.14 arc(296.05,279.43) v3(296.45,278.83) ; S1_PCIE_TX_N[6].3 250.19,280.14 arc(250.33,279.43) v3(250.73,278.83) ; S1_PCIE_TX_P[5].4 265.43,274.47 arc(265.57,275.18) v3(265.97,275.78) ; S1_PCIE_TX_N[7].2 240.03,281.59 arc(239.73,280.09) v3(238.89,278.83) ; S1_PCIE_TX_N[1].5 331.47,273.02 arc(331.17,274.51) v3(330.33,275.78) ; S1_PCIE_TX_N[4].3 280.67,280.14 arc(280.81,279.43) v3(281.21,278.83) ; S1_PCIE_TX_P[0].2 346.71,281.59 arc(346.41,280.09) v3(345.57,278.83) ; S1_PCIE_TX_N[5].3 265.43,280.14 arc(265.57,279.43) v3(265.97,278.83) ; S1_PCIE_TX_P[7].5 240.03,273.02 arc(239.73,274.51) v3(238.89,275.78) ; C418.2 v1(291.69,183.61) ; S1_PCIE_TX_N[1].4 326.39,274.47 arc(326.53,275.18) v3(326.93,275.78) ; S1_PCIE_TX_P[7].4 234.95,274.47 arc(235.09,275.18) v3(235.49,275.78) ; S1_PCIE_TX_N[5].2 270.51,281.59 arc(270.21,280.09) v3(269.37,278.83) ; S1_PCIE_TX_P[6].5 255.27,273.02 arc(254.97,274.51) v3(254.13,275.78) ; S1_PCIE_TX_N[0].5 346.71,273.02 arc(346.41,274.51) v3(345.57,275.78) ; S1_PCIE_TX_N[3].2 300.99,281.59 arc(300.69,280.09) v3(299.85,278.83) ; S1_PCIE_TX_P[1].3 326.39,280.14 arc(326.53,279.43) v3(326.93,278.83) ; S1_PCIE_TX_N[7].3 234.95,280.14 arc(235.09,279.43) v3(235.49,278.83) ; S1_PCIE_TX_P[5].5 270.51,273.02 arc(270.21,274.51) v3(269.37,275.78) ; S1_PCIE_TX_P[3].5 300.99,273.02 arc(300.69,274.51) v3(299.85,275.78) ; S1_PCIE_TX_N[4].2 285.75,281.59 arc(285.45,280.09) v3(284.61,278.83)
  BOTTOM w0.152: v1(308.19,228.6) C198.2 ; v1(308.19,226.82) C375.2
  BOTTOM w0.508: OSC1.2 v1(290.75,189.46) ; C286.2 v1(395.22,220.85) ; C289.2 v1(395.22,244.98)
  vias: v1(171.91,297.69) v1(171.91,294.89) v1(192.9,135.07) v1(192.99,137.92) v1(223.39,242.44) v1(223.39,228.73) v1(223.39,203.58) v1(223.52,199.01) v1(223.52,185.29) v1(223.52,160.15) v1(241.55,231.14) v1(241.55,225.3) v1(241.55,219.46) v1(241.55,213.61) v1(241.55,208.03) v1(241.55,201.93) v1(241.62,195.45) v1(241.62,189.61) v1(241.62,183.77) v1(241.62,177.93) v1(241.62,172.08) v1(241.62,166.24) v1(242.19,149.54) v1(245.62,236.47) v1(257.68,149.54) v1(258.13,222) v1(258.83,231.14) v1(259.35,227.33) v1(260.03,218.44) v1(260.1,196.6) v1(260.62,200.91) v1(263.93,222) v1(264.83,218.44) v1(264.83,216.66) v1(264.83,214.88) v1(264.99,227.33) v1(265.09,224.03) v1(265.75,200.91) v1(266.06,166.12) v1(266.14,211.33) v1(269.56,222) v1(269.66,227.33) v1(269.66,223.77) v1(269.75,175.07) v1(269.91,200.91) v1(270.07,220.22) v1(270.07,218.44) v1(270.07,216.66) v1(270.07,214.88) v1(270.07,213.11) v1(270.07,211.33) v1(270.07,209.55) v1(270.07,207.77) v1(270.07,205.99) v1(270.07,204.22) v1(270.26,225.55) v1(270.51,167.03) v1(272.54,183.64) v1(273.05,179.74) v1(273.3,175.07) v1(273.47,225.55) v1(273.47,223.77) v1(273.47,222) v1(273.47,220.22) v1(273.47,218.44) v1(273.47,216.66) v1(273.47,214.88) v1(273.47,213.11) v1(273.47,211.33) v1(273.47,209.55) v1(273.47,207.77) v1(273.47,205.99) v1(273.47,204.22) v1(273.47,202.44) v1(273.69,149.54) v1(274.33,227.33) v1(274.32,167.33) v1(275.33,200.91) v1(276.61,189.55) v1(276.61,184.17) v1(276.86,179.74) v1(276.86,175.07) v1(276.86,167.43) v1(278.13,198.13) v1(278.13,193.97) v1(278.43,225.43) v1(278.43,221.43) v1(278.43,217.43) v1(278.43,215.03) v1(278.43,211.03) v1(278.43,207.83) v1(278.76,167.77) v1(279.23,223.83) v1(279.23,219.83) v1(279.23,215.83) v1(279.23,213.43) v1(279.23,206.23) v1(279.23,203.83) v1(279.91,197.27) v1(279.91,193.97) v1(279.91,189.8) v1(279.91,184.17) v1(279.91,179.74) v1(279.91,175.43) v1(280.03,226.23) v1(280.03,222.23) v1(280.03,218.23) v1(280.03,209.43) v1(280.03,204.63) v1(280.03,202.23) v1(280.03,149.54) v1(280.83,225.43) v1(280.83,221.43) v1(280.83,219.03) v1(280.83,215.83) v1(280.83,212.63) v1(280.83,207.03) v1(281.63,223.83) v1(281.63,219.83) v1(281.63,217.43) v1(281.63,214.23) v1(281.63,210.23) v1(281.63,205.43) v1(281.63,203.03) v1(281.69,197.27) v1(281.69,194.57) v1(282.43,226.23) v1(282.43,222.23) v1(282.43,211.83) v1(282.43,208.63) v1(283.23,223.03) v1(283.23,221.43) v1(283.23,219.83) v1(283.23,218.23) v1(283.23,216.63) v1(283.23,215.03) v1(283.23,213.43) v1(283.23,211.83) v1(283.23,210.23) v1(283.23,208.63) v1(283.23,207.03) v1(283.23,206.23) v1(283.23,203.83) v1(283.46,197.27) v1(283.46,193.97) v1(284.03,224.63) v1(284.03,223.83) v1(284.03,223.03) v1(284.03,222.23) v1(284.03,220.63) v1(284.03,219.03) v1(284.03,217.43) v1(284.03,215.83) v1(284.03,214.23) v1(284.03,212.63) v1(284.03,211.03) v1(284.03,209.43) v1(284.03,207.83) v1(284.03,207.03) v1(284.03,204.63) v1(284.03,202.23) v1(284.83,227.03) v1(284.83,226.23) v1(284.83,225.43) v1(284.83,223.03) v1(284.83,221.43) v1(284.83,219.83) v1(284.83,218.23) v1(284.83,216.63) v1(284.83,215.03) v1(284.83,213.43) v1(284.83,211.83) v1(284.83,210.23) v1(284.83,208.63) v1(284.83,207.03) v1(285.24,197.27) v1(285.24,193.87) v1(285.63,225.43) v1(285.63,224.63) v1(285.63,223.83) v1(285.63,223.03) v1(285.63,222.23) v1(285.63,221.43) v1(285.63,220.63) v1(285.63,219.83) v1(285.63,219.03) v1(285.63,218.23) v1(285.63,217.43) v1(285.63,215.83) v1(285.63,214.23) v1(285.63,212.63) v1(285.63,211.03) v1(285.63,209.43) v1(285.63,207.83) v1(285.63,205.43) v1(285.63,203.03) v1(286.43,227.03) v1(286.43,226.23) v1(286.43,225.43) v1(286.43,223.03) v1(286.43,222.23) v1(286.43,221.43) v1(286.43,219.83) v1(286.43,218.23) v1(286.43,216.63) v1(286.43,215.03) v1(286.43,213.43) v1(286.43,211.83) v1(286.43,210.23) v1(286.43,208.63) v1(286.43,207.83) v1(286.43,207.03) v1(287.02,197.27) v1(287.02,193.87) v1(287.23,225.43) v1(287.23,224.63) v1(287.23,223.83) v1(287.23,223.03) v1(287.23,222.23) v1(287.23,221.43) v1(287.23,220.63) v1(287.23,219.03) v1(287.23,217.43) v1(287.23,215.83) v1(287.23,214.23) v1(287.23,212.63) v1(287.23,211.03) v1(287.23,209.43) v1(287.23,207.83) v1(287.23,207.03) v1(287.23,203.83) v1(287.65,231.83) v1(288.03,227.03) v1(288.03,226.23) v1(288.03,225.43) v1(288.03,223.03) v1(288.03,222.23) v1(288.03,220.63) v1(288.03,219.83) v1(288.03,218.23) v1(288.03,216.63) v1(288.03,215.03) v1(288.03,213.43) v1(288.03,211.83) v1(288.03,210.23) v1(288.03,208.63) v1(288.03,207.03) v1(288.03,202.23) v1(288.04,173.8) v1(288.83,225.43) v1(288.83,224.63) v1(288.83,223.83) v1(288.83,223.03) v1(288.83,222.23) v1(288.83,221.43) v1(288.83,220.63) v1(288.83,219.03) v1(288.83,217.43) v1(288.83,215.83) v1(288.83,214.23) v1(288.83,212.63) v1(288.83,211.03) v1(288.83,209.43) v1(288.83,207.83) v1(288.83,207.03) v1(288.8,197.27) v1(288.8,193.87) v1(289.63,227.03) v1(289.63,226.23) v1(289.63,225.43) v1(289.63,223.03) v1(289.63,220.63) v1(289.63,219.83) v1(289.63,218.23) v1(289.63,216.63) v1(289.63,215.03) v1(289.63,213.43) v1(289.63,211.83) v1(289.63,210.23) v1(289.63,208.63) v1(289.63,207.03) v1(289.63,203.03) v1(290.43,225.43) v1(290.43,224.63) v1(290.43,223.83) v1(290.43,223.03) v1(290.43,222.23) v1(290.43,221.43) v1(290.43,220.63) v1(290.43,219.03) v1(290.43,217.43) v1(290.43,215.83) v1(290.43,214.23) v1(290.43,212.63) v1(290.43,211.03) v1(290.43,209.43) v1(290.43,207.83) v1(290.43,207.03) v1(290.43,203.83) v1(290.58,197.27) v1(290.58,193.87) v1(291.23,227.03) v1(291.23,226.23) v1(291.23,225.43) v1(291.23,223.03) v1(291.23,222.23) v1(291.23,220.63) v1(291.23,219.83) v1(291.23,218.23) v1(291.23,216.63) v1(291.23,215.03) v1(291.23,213.43) v1(291.23,211.83) v1(291.23,210.23) v1(291.23,208.63) v1(291.23,207.03) v1(291.34,179.24) v1(291.46,149.54) v1(291.95,182.48) v1(292.03,225.43) v1(292.03,224.63) v1(292.03,223.83) v1(292.03,223.03) v1(292.03,222.23) v1(292.03,221.43) v1(292.03,220.63) v1(292.03,219.03) v1(292.03,217.43) v1(292.03,215.83) v1(292.03,214.23) v1(292.03,212.63) v1(292.03,211.03) v1(292.03,209.43) v1(292.03,207.83) v1(292.03,207.03) v1(292.03,203.03) v1(292.35,197.27) v1(292.35,193.87) v1(292.83,227.03) v1(292.83,226.23) v1(292.83,225.43) v1(292.83,223.03) v1(292.83,220.63) v1(292.83,219.83) v1(292.83,218.23) v1(292.83,216.63) v1(292.83,215.03) v1(292.83,213.43) v1(292.83,211.83) v1(292.83,210.23) v1(292.83,208.63) v1(292.83,207.03) v1(293.12,179.84) v1(293.63,225.43) v1(293.63,224.63) v1(293.63,223.83) v1(293.63,223.03) v1(293.63,222.23) v1(293.63,221.43) v1(293.63,220.63) v1(293.63,219.03) v1(293.63,217.43) v1(293.63,215.83) v1(293.63,214.23) v1(293.63,212.63) v1(293.63,211.03) v1(293.63,209.43) v1(293.63,207.83) v1(293.63,207.03) v1(293.63,202.23) v1(294.13,197.27) v1(294.13,193.87) v1(294.43,227.03) v1(294.43,226.23) v1(294.43,225.43) v1(294.43,223.03) v1(294.43,222.23) v1(294.43,221.43) v1(294.43,219.83) v1(294.43,218.23) v1(294.43,216.63) v1(294.43,215.03) v1(294.43,213.43) v1(294.43,211.83) v1(294.43,210.23) v1(294.43,208.63) v1(294.43,207.03) v1(294.43,203.83) v1(294.39,172.72) v1(295.23,225.43) v1(295.23,224.63) v1(295.23,223.83) v1(295.23,223.03) v1(295.23,222.23) v1(295.23,221.43) v1(295.23,220.63) v1(295.23,219.03) v1(295.23,217.43) v1(295.23,215.83) v1(295.23,214.23) v1(295.23,212.63) v1(295.23,211.03) v1(295.23,209.43) v1(295.23,207.83) v1(295.23,207.03) v1(295.91,197.27) v1(295.91,193.87) v1(296.03,227.03) v1(296.03,226.23) v1(296.03,225.43) v1(296.03,223.03) v1(296.03,222.23) v1(296.03,221.43) v1(296.03,220.63) v1(296.03,219.83) v1(296.03,219.03) v1(296.03,218.23) v1(296.03,216.63) v1(296.03,215.03) v1(296.03,213.43) v1(296.03,211.83) v1(296.03,210.23) v1(296.03,208.63) v1(296.03,207.83) v1(296.03,207.03) v1(296.03,205.43) v1(296.03,203.03) v1(296.54,149.54) v1(296.83,225.43) v1(296.83,224.63) v1(296.83,223.83) v1(296.83,223.03) v1(296.83,222.23) v1(296.83,220.63) v1(296.83,219.03) v1(296.83,217.43) v1(296.83,215.83) v1(296.83,214.23) v1(296.83,212.63) v1(296.83,211.03) v1(296.83,209.43) v1(296.83,207.83) v1(297.63,227.03) v1(297.63,226.23) v1(297.63,225.43) v1(297.63,221.43) v1(297.63,219.83) v1(297.63,218.23) v1(297.63,216.63) v1(297.63,215.03) v1(297.63,213.43) v1(297.63,211.83) v1(297.63,210.23) v1(297.63,208.63) v1(297.63,207.03) v1(297.63,204.63) v1(297.63,202.23) v1(297.69,197.27) v1(297.69,193.87) v1(298.43,222.23) v1(298.43,220.63) v1(298.43,219.03) v1(298.43,217.43) v1(298.43,215.83) v1(298.43,214.23) v1(298.43,212.63) v1(298.43,211.03) v1(298.43,209.43) v1(298.43,207.83) v1(298.43,206.23) v1(298.43,203.83) v1(298.7,231.83) v1(299.08,172.85) v1(299.23,226.23) v1(299.23,222.23) v1(299.23,211.83) v1(299.23,208.63) v1(299.47,197.27) v1(299.47,193.87) v1(299.97,166.5) v1(300.03,223.83) v1(300.03,219.83) v1(300.03,217.43) v1(300.03,214.23) v1(300.03,210.23) v1(300.03,205.43) v1(300.03,203.03) v1(300.83,225.43) v1(300.83,221.43) v1(300.83,219.03) v1(300.83,215.83) v1(300.83,212.63) v1(300.83,207.03) v1(300.99,172.51) v1(301.24,197.27) v1(301.24,193.87) v1(301.63,226.23) v1(301.63,222.23) v1(301.63,218.23) v1(301.63,209.43) v1(301.63,204.63) v1(301.63,202.23) v1(302.43,223.83) v1(302.43,219.83) v1(302.43,215.83) v1(302.43,213.43) v1(302.43,206.23) v1(302.43,203.83) v1(302.89,172.41) v1(303.23,225.43) v1(303.23,221.43) v1(303.23,217.43) v1(303.23,215.03) v1(303.23,211.03) v1(303.23,207.83) v1(303.28,198.13) v1(303.28,193.97) v1(303.28,190.06) v1(303.28,184.93) v1(303.28,179.07) v1(303.53,167) v1(305.82,197.87) v1(305.82,193.97) v1(305.82,190.06) v1(305.82,184.93) v1(307.33,201.93) v1(307.97,149.54) v1(308.19,225.04) v1(308.19,223.27) v1(308.19,221.49) v1(308.19,219.71) v1(308.19,217.93) v1(308.19,216.15) v1(308.19,214.38) v1(308.19,212.6) v1(308.19,209.04) v1(308.19,207.26) v1(308.19,205.49) v1(308.19,203.71) v1(309.63,184.4) v1(311.59,228.6) v1(311.59,226.82) v1(311.59,225.04) v1(311.59,223.27) v1(311.59,221.49) v1(311.59,219.71) v1(311.59,217.93) v1(311.59,216.15) v1(311.59,214.38) v1(311.59,212.6) v1(311.59,210.82) v1(311.59,209.04) v1(311.59,207.26) v1(311.59,205.49) v1(311.59,203.71) v1(313.48,167.26) v1(313.56,149.54) v1(314.32,164.91) v1(314.99,228.6) v1(314.99,226.82) v1(314.99,225.04) v1(314.99,223.27) v1(318.44,211.33) v1(319.96,204.98) v1(320.53,231.39) v1(320.66,208.53) v1(320.8,234.95) v1(321.7,194.71) v1(322.64,191.52) v1(323.19,188.72) v1(323.72,184.91) v1(325.06,208.53) v1(325.06,204.98) v1(325.49,194.56) v1(325.75,167.26) v1(325.75,164.91) v1(327.79,190.06) v1(329.4,194.56) v1(331.34,204.98) v1(333.16,167.26) v1(334.01,164.91) v1(335.41,188.98) v1(336.16,247.4) v1(336.16,243.59) v1(336.16,230.12) v1(336.16,226.31) v1(336.68,249.17) v1(336.68,231.9) v1(338.78,239.09) v1(338.78,237.82) v1(338.78,235.53) v1(339.16,245.15) v1(339.16,227.88) v1(340.74,245.63) v1(340.74,228.35) v1(340.68,220.98) v1(340.78,218.44) v1(341.13,215.9) v1(343.79,210.82) v1(343.79,204.98) v1(343.79,198.37) v1(345.43,167.26) v1(345.44,164.91) v1(346.66,133.6) v1(346.73,130.75) v1(348.59,216.53) v1(348.87,220.98) v1(352.14,235.53) v1(353.24,241.37) v1(353.24,237.56) v1(354.12,167.26) v1(354.65,220.98) v1(354.75,218.44) v1(354.97,216.28) v1(354.96,164.91) v1(356.03,242.9) v1(356.23,238.87) v1(357.67,210.82) v1(358.07,239.86) v1(361.93,216.53) v1(362.2,220.98) v1(364.36,234.96) v1(366.39,234.1) v1(366.39,227.84) v1(366.39,167.26) v1(366.39,164.91) v1(369.19,234) v1(372.24,233.45) v1(378.15,214) v1(378.15,204.85) v1(378.15,193.17) v1(378.15,188.09) v1(378.15,176.66) v1(378.15,172.34) v1(378.47,257.3) v1(378.47,243.59) v1(378.47,218.44) v1(390.65,253.23) v1(390.65,231.39) v1(393.32,255.27) v1(393.32,233.43) v1(394.08,255.27) v1(394.08,233.43) v1(397.07,252.6) v1(397.07,251.84) v1(397.07,245.75) v1(397.07,244.98) v1(397.07,233.04) v1(397.07,232.28) v1(397.07,221.62) v1(397.07,220.85) v1(403.43,133.6) v1(403.43,130.56) v1(421.89,275.64) v1(425.96,275.64) v2(324.93,246.95) v2(324.93,244.79) v2(324.93,229.68) v2(324.93,227.52) v2(325.76,249.37) v2(325.76,242.38) v2(325.76,232.09) v2(325.76,225.11) v2(327.91,246.95) v2(327.91,244.79) v2(327.91,229.68) v2(327.91,227.52) v2(328.29,250.19) v2(328.29,241.55) v2(328.29,232.92) v2(328.29,224.28) v2(328.68,246.95) v2(328.68,244.79) v2(328.68,229.68) v2(328.68,227.52) v2(330.83,249.37) v2(330.83,242.38) v2(330.83,232.09) v2(330.83,225.11) v2(331.66,246.95) v2(331.66,244.79) v2(331.66,229.68) v2(331.66,227.52) v3(16.51,290.7) v3(16.51,285.62) v3(16.51,280.54) v3(16.51,275.46) v3(16.51,270.38) v3(16.51,265.3) v3(16.51,260.22) v3(16.51,255.14) v3(16.51,250.06) v3(16.51,239.9) v3(16.51,234.82) v3(16.51,229.74) v3(16.51,224.66) v3(16.51,219.58) v3(16.51,214.5) v3(16.51,209.42) v3(16.51,204.34) v3(16.51,199.26) v3(16.51,194.18) v3(16.51,189.1) v3(16.51,184.02) v3(16.51,178.94) v3(16.51,173.86) v3(16.51,168.78) v3(16.51,163.7) v3(16.51,158.62) v3(16.51,153.54) v3(16.51,148.46) v3(16.51,143.38) v3(16.51,138.3) v3(21.59,295.78) v3(21.59,290.7) v3(21.59,285.62) v3(21.59,280.54) v3(21.59,275.46) v3(21.59,270.38) v3(21.59,265.3) v3(21.59,260.22) v3(21.59,255.14) v3(21.59,244.98) v3(21.59,234.82) v3(21.59,229.74) v3(21.59,224.66) v3(21.59,219.58) v3(21.59,214.5) v3(21.59,209.42) v3(21.59,204.34) v3(21.59,199.26) v3(21.59,194.18) v3(21.59,189.1) v3(21.59,184.02) v3(21.59,178.94) v3(21.59,173.86) v3(21.59,168.78) v3(21.59,163.7) v3(21.59,158.62) v3(21.59,153.54) v3(21.59,148.46) v3(21.59,143.38) v3(21.59,138.3) v3(26.67,295.78) v3(26.67,290.7) v3(26.67,285.62) v3(26.67,280.54) v3(26.67,275.46) v3(26.67,270.38) v3(26.67,265.3) v3(26.67,260.22) v3(26.67,255.14) v3(26.67,250.06) v3(26.67,244.98) v3(26.67,229.74) v3(26.67,224.66) v3(26.67,219.58) v3(26.67,214.5) v3(26.67,209.42) v3(26.67,204.34) v3(26.67,199.26) v3(26.67,194.18) v3(26.67,189.1) v3(26.67,184.02) v3(26.67,178.94) v3(26.67,173.86) v3(26.67,168.78) v3(26.67,163.7) v3(26.67,158.62) v3(26.67,153.54) v3(26.67,148.46) v3(26.67,143.38) v3(26.67,138.3) v3(31.75,295.78) v3(31.75,290.7) v3(31.75,285.62) v3(31.75,280.54) v3(31.75,275.46) v3(31.75,270.38) v3(31.75,265.3) v3(31.75,260.22) v3(31.75,255.14) v3(31.75,250.06) v3(31.75,244.98) v3(31.75,239.9) v3(31.75,234.82) v3(31.75,229.74) v3(31.75,224.66) v3(31.75,219.58) v3(31.75,214.5) v3(31.75,209.42) v3(31.75,204.34) v3(31.75,199.26) v3(31.75,194.18) v3(31.75,189.1) v3(31.75,184.02) v3(31.75,178.94) v3(31.75,173.86) v3(31.75,168.78) v3(31.75,163.7) v3(31.75,158.62) v3(31.75,153.54) v3(31.75,148.46) v3(31.75,143.38) v3(36.83,295.78) v3(36.83,290.7) v3(36.83,285.62) v3(36.83,280.54) v3(36.83,275.46) v3(36.83,270.38) v3(36.83,265.3) v3(36.83,260.22) v3(36.83,255.14) v3(36.83,250.06) v3(36.83,244.98) v3(36.83,239.9) v3(36.83,234.82) v3(36.83,229.74) v3(36.83,224.66) v3(36.83,209.42) v3(36.83,199.26) v3(36.83,189.1) v3(36.83,184.02) v3(36.83,168.78) v3(36.83,158.62) v3(36.83,148.46) v3(36.83,143.38) v3(36.83,138.3) v3(41.91,295.78) v3(41.91,290.7) v3(41.91,285.62) v3(41.91,280.54) v3(41.91,275.46) v3(41.91,270.38) v3(41.91,265.3) v3(41.91,260.22) v3(41.91,255.14) v3(41.91,250.06) v3(41.91,244.98) v3(41.91,239.9) v3(41.91,234.82) v3(41.91,229.74) v3(41.91,143.38) v3(41.91,138.3) v3(46.99,295.78) v3(46.99,290.7) v3(46.99,285.62) v3(46.99,280.54) v3(46.99,275.46) v3(46.99,270.38) v3(46.99,265.3) v3(46.99,260.22) v3(46.99,255.14) v3(46.99,250.06) v3(46.99,244.98) v3(46.99,239.9) v3(46.99,234.82) v3(46.99,229.74) v3(46.99,143.38) v3(46.99,138.3) v3(52.07,295.78) v3(52.07,285.62) v3(52.07,280.54) v3(52.07,275.46) v3(52.07,270.38) v3(52.07,265.3) v3(52.07,260.22) v3(52.07,255.14) v3(52.07,250.06) v3(52.07,244.98) v3(52.07,239.9) v3(52.07,234.82) v3(52.07,229.74) v3(52.07,143.38) v3(52.07,138.3) v3(57.15,285.62) v3(57.15,280.54) v3(57.15,275.46) v3(57.15,270.38) v3(57.15,265.3) v3(57.15,260.22) v3(57.15,255.14) v3(57.15,250.06) v3(57.15,244.98) v3(57.15,239.9) v3(57.15,234.82) v3(57.15,229.74) v3(57.15,209.42) v3(57.15,189.1) v3(57.15,168.78) v3(57.15,148.46) v3(57.15,143.38) v3(57.15,138.3) v3(62.23,295.78) v3(62.23,280.54) v3(62.23,275.46) v3(62.23,270.38) v3(62.23,265.3) v3(62.23,260.22) v3(62.23,255.14) v3(62.23,250.06) v3(62.23,244.98) v3(62.23,239.9) v3(62.23,234.82) v3(62.23,229.74) v3(62.23,209.42) v3(62.23,189.1) v3(62.23,168.78) v3(62.23,148.46) v3(62.23,143.38) v3(62.23,138.3) v3(67.31,295.78) v3(67.31,290.7) v3(67.31,285.62) v3(67.31,280.54) v3(67.31,275.46) v3(67.31,270.38) v3(67.31,265.3) v3(67.31,260.22) v3(67.31,255.14) v3(67.31,250.06) v3(67.31,244.98) v3(67.31,239.9) v3(67.31,234.82) v3(67.31,229.74) v3(67.31,189.1) v3(67.31,184.02) v3(67.31,168.78) v3(67.31,148.46) v3(67.31,143.38) v3(67.31,138.3) v3(72.39,295.78) v3(72.39,290.7) v3(72.39,285.62) v3(72.39,280.54) v3(72.39,275.46) v3(72.39,270.38) v3(72.39,265.3) v3(72.39,260.22) v3(72.39,255.14) v3(72.39,250.06) v3(72.39,244.98) v3(72.39,239.9) v3(72.39,234.82) v3(72.39,229.74) v3(72.39,224.66) v3(72.39,189.1) v3(72.39,184.02) v3(72.39,168.78) v3(72.39,148.46) v3(72.39,143.38) v3(72.39,138.3) v3(77.47,295.78) v3(77.47,290.7) v3(77.47,285.62) v3(77.47,280.54) v3(77.47,275.46) v3(77.47,270.38) v3(77.47,265.3) v3(77.47,260.22) v3(77.47,255.14) v3(77.47,250.06) v3(77.47,244.98) v3(77.47,239.9) v3(77.47,234.82) v3(77.47,229.74) v3(77.47,224.66) v3(77.47,219.58) v3(77.47,214.5) v3(77.47,209.42) v3(77.47,204.34) v3(77.47,199.26) v3(77.47,194.18) v3(77.47,189.1) v3(77.47,184.02) v3(77.47,178.94) v3(77.47,173.86) v3(77.47,168.78) v3(77.47,163.7) v3(77.47,158.62) v3(77.47,153.54) v3(77.47,148.46) v3(77.47,143.38) v3(77.47,138.3) v3(82.55,295.78) v3(82.55,290.7) v3(82.55,285.62) v3(82.55,280.54) v3(82.55,275.46) v3(82.55,270.38) v3(82.55,265.3) v3(82.55,260.22) v3(82.55,255.14) v3(82.55,250.06) v3(82.55,244.98) v3(82.55,239.9) v3(82.55,234.82) v3(82.55,229.74) v3(82.55,224.66) v3(82.55,219.58) v3(82.55,214.5) v3(82.55,209.42) v3(82.55,204.34) v3(82.55,199.26) v3(82.55,194.18) v3(82.55,189.1) v3(82.55,184.02) v3(82.55,178.94) v3(82.55,173.86) v3(82.55,168.78) v3(82.55,163.7) v3(82.55,158.62) v3(82.55,153.54) v3(82.55,148.46) v3(82.55,143.38) v3(82.55,138.3) v3(87.63,295.78) v3(87.63,290.7) v3(87.63,285.62) v3(87.63,280.54) v3(87.63,275.46) v3(87.63,270.38) v3(87.63,265.3) v3(87.63,260.22) v3(87.63,255.14) v3(87.63,250.06) v3(87.63,244.98) v3(87.63,239.9) v3(87.63,234.82) v3(87.63,229.74) v3(87.63,224.66) v3(87.63,219.58) v3(87.63,214.5) v3(87.63,209.42) v3(87.63,204.34) v3(87.63,199.26) v3(87.63,194.18) v3(87.63,189.1) v3(87.63,184.02) v3(87.63,178.94) v3(87.63,173.86) v3(87.63,168.78) v3(87.63,163.7) v3(87.63,158.62) v3(87.63,153.54) v3(87.63,148.46) v3(87.63,143.38) v3(87.63,138.3) v3(92.71,295.78) v3(92.71,290.7) v3(92.71,285.62) v3(92.71,280.54) v3(92.71,275.46) v3(92.71,270.38) v3(92.71,265.3) v3(92.71,260.22) v3(92.71,255.14) v3(92.71,250.06) v3(92.71,244.98) v3(92.71,239.9) v3(92.71,234.82) v3(92.71,229.74) v3(92.71,224.66) v3(92.71,219.58) v3(92.71,214.5) v3(92.71,209.42) v3(92.71,204.34) v3(92.71,199.26) v3(92.71,194.18) v3(92.71,189.1) v3(92.71,184.02) v3(92.71,178.94) v3(92.71,173.86) v3(92.71,168.78) v3(92.71,163.7) v3(92.71,158.62) v3(92.71,153.54) v3(92.71,148.46) v3(92.71,143.38) v3(92.71,138.3) v3(97.79,285.62) v3(97.79,280.54) v3(97.79,275.46) v3(97.79,270.38) v3(97.79,265.3) v3(97.79,260.22) v3(97.79,255.14) v3(97.79,250.06) v3(97.79,244.98) v3(97.79,239.9) v3(97.79,234.82) v3(97.79,229.74) v3(97.79,224.66) v3(97.79,219.58) v3(97.79,214.5) v3(97.79,209.42) v3(97.79,204.34) v3(97.79,199.26) v3(97.79,194.18) v3(97.79,189.1) v3(97.79,184.02) v3(97.79,178.94) v3(97.79,173.86) v3(97.79,168.78) v3(97.79,163.7) v3(97.79,158.62) v3(97.79,153.54) v3(97.79,148.46) v3(97.79,143.38) v3(97.79,138.3) v3(102.87,285.62) v3(102.87,280.54) v3(102.87,275.46) v3(102.87,270.38) v3(102.87,265.3) v3(102.87,260.22) v3(102.87,255.14) v3(102.87,250.06) v3(102.87,244.98) v3(102.87,239.9) v3(102.87,234.82) v3(102.87,229.74) v3(102.87,224.66) v3(102.87,219.58) v3(102.87,214.5) v3(102.87,209.42) v3(102.87,204.34) v3(102.87,199.26) v3(102.87,194.18) v3(102.87,189.1) v3(102.87,184.02) v3(102.87,178.94) v3(102.87,173.86) v3(102.87,168.78) v3(102.87,163.7) v3(102.87,158.62) v3(102.87,153.54) v3(102.87,148.46) v3(102.87,143.38) v3(102.87,138.3) v3(107.95,295.78) v3(107.95,290.7) v3(107.95,285.62) v3(107.95,280.54) v3(107.95,275.46) v3(107.95,270.38) v3(107.95,265.3) v3(107.95,260.22) v3(107.95,255.14) v3(107.95,250.06) v3(107.95,244.98) v3(107.95,239.9) v3(107.95,234.82) v3(107.95,229.74) v3(107.95,224.66) v3(107.95,219.58) v3(107.95,214.5) v3(107.95,209.42) v3(107.95,204.34) v3(107.95,199.26) v3(107.95,194.18) v3(107.95,189.1) v3(107.95,184.02) v3(107.95,178.94) v3(107.95,173.86) v3(107.95,168.78) v3(107.95,163.7) v3(107.95,158.62) v3(107.95,153.54) v3(107.95,148.46) v3(107.95,143.38) v3(107.95,138.3) v3(113.03,295.78) v3(113.03,290.7) v3(113.03,285.62) v3(113.03,280.54) v3(113.03,275.46) v3(113.03,270.38) v3(113.03,265.3) v3(113.03,260.22) v3(113.03,255.14) v3(113.03,250.06) v3(113.03,244.98) v3(113.03,239.9) v3(113.03,234.82) v3(113.03,229.74) v3(113.03,224.66) v3(113.03,219.58) v3(113.03,214.5) v3(113.03,209.42) v3(113.03,204.34) v3(113.03,199.26) v3(113.03,194.18) v3(113.03,189.1) v3(113.03,184.02) v3(113.03,178.94) v3(113.03,173.86) v3(113.03,168.78) v3(113.03,163.7) v3(113.03,158.62) v3(113.03,153.54) v3(113.03,148.46) v3(113.03,143.38) v3(113.03,138.3) v3(118.11,295.78) v3(118.11,290.7) v3(118.11,285.62) v3(118.11,280.54) v3(118.11,275.46) v3(118.11,270.38) v3(118.11,265.3) v3(118.11,260.22) v3(118.11,255.14) v3(118.11,250.06) v3(118.11,244.98) v3(118.11,239.9) v3(118.11,234.82) v3(118.11,229.74) v3(118.11,224.66) v3(118.11,219.58) v3(118.11,214.5) v3(118.11,209.42) v3(118.11,204.34) v3(118.11,199.26) v3(118.11,194.18) v3(118.11,189.1) v3(118.11,184.02) v3(118.11,178.94) v3(118.11,173.86) v3(118.11,168.78) v3(118.11,163.7) v3(118.11,158.62) v3(118.11,153.54) v3(118.11,148.46) v3(118.11,143.38) v3(118.11,138.3) v3(123.19,295.78) v3(123.19,290.7) v3(123.19,285.62) v3(123.19,280.54) v3(123.19,275.46) v3(123.19,270.38) v3(123.19,265.3) v3(123.19,260.22) v3(123.19,255.14) v3(123.19,250.06) v3(123.19,244.98) v3(123.19,239.9) v3(123.19,234.82) v3(123.19,229.74) v3(123.19,224.66) v3(123.19,219.58) v3(123.19,214.5) v3(123.19,209.42) v3(123.19,204.34) v3(123.19,199.26) v3(123.19,194.18) v3(123.19,189.1) v3(123.19,184.02) v3(123.19,178.94) v3(123.19,173.86) v3(123.19,168.78) v3(123.19,163.7) v3(123.19,158.62) v3(123.19,153.54) v3(123.19,148.46) v3(123.19,143.38) v3(123.19,138.3) v3(128.27,295.78) v3(128.27,290.7) v3(128.27,285.62) v3(128.27,280.54) v3(128.27,275.46) v3(128.27,270.38) v3(128.27,265.3) v3(128.27,260.22) v3(128.27,255.14) v3(128.27,250.06) v3(128.27,244.98) v3(128.27,239.9) v3(128.27,234.82) v3(128.27,229.74) v3(128.27,224.66) v3(128.27,219.58) v3(128.27,214.5) v3(128.27,209.42) v3(128.27,204.34) v3(128.27,199.26) v3(128.27,194.18) v3(128.27,189.1) v3(128.27,184.02) v3(128.27,178.94) v3(128.27,173.86) v3(128.27,168.78) v3(128.27,163.7) v3(128.27,158.62) v3(128.27,153.54) v3(128.27,148.46) v3(128.27,143.38) v3(128.27,138.3) v3(158.75,295.78) v3(158.75,290.7) v3(158.75,285.62) v3(158.75,280.54) v3(158.75,275.46) v3(158.75,270.38) v3(158.75,265.3) v3(158.75,260.22) v3(158.75,255.14) v3(158.75,250.06) v3(158.75,244.98) v3(158.75,239.9) v3(158.75,153.54) v3(158.75,148.46) v3(158.75,143.38) v3(158.75,138.3) v3(163.83,295.78) v3(163.83,290.7) v3(163.83,285.62) v3(163.83,280.54) v3(163.83,275.46) v3(163.83,270.38) v3(163.83,265.3) v3(163.83,260.22) v3(163.83,255.14) v3(163.83,250.06) v3(163.83,244.98) v3(163.83,239.9) v3(163.83,234.82) v3(163.83,194.18) v3(163.83,153.54) v3(163.83,148.46) v3(163.83,143.38) v3(163.83,138.3) v3(168.91,295.78) v3(168.91,290.7) v3(168.91,285.62) v3(168.91,280.54) v3(168.91,275.46) v3(168.91,270.38) v3(168.91,265.3) v3(168.91,260.22) v3(168.91,255.14) v3(168.91,250.06) v3(168.91,244.98) v3(168.91,239.9) v3(168.91,234.82) v3(168.91,229.74) v3(168.91,224.66) v3(168.91,219.58) v3(168.91,214.5) v3(168.91,209.42) v3(168.91,204.34) v3(168.91,199.26) v3(168.91,194.18) v3(168.91,189.1) v3(168.91,184.02) v3(168.91,178.94) v3(168.91,153.54) v3(168.91,148.46) v3(168.91,143.38) v3(168.91,138.3) v3(173.99,295.78) v3(173.99,290.7) v3(173.99,285.62) v3(173.99,280.54) v3(173.99,275.46) v3(173.99,270.38) v3(173.99,265.3) v3(173.99,260.22) v3(173.99,255.14) v3(173.99,250.06) v3(173.99,244.98) v3(173.99,239.9) v3(173.99,234.82) v3(173.99,229.74) v3(173.99,224.66) v3(173.99,219.58) v3(173.99,214.5) v3(173.99,209.42) v3(173.99,204.34) v3(173.99,199.26) v3(173.99,194.18) v3(173.99,153.54) v3(173.99,148.46) v3(173.99,143.38) v3(173.99,138.3) v3(179.07,290.7) v3(179.07,285.62) v3(179.07,280.54) v3(179.07,275.46) v3(179.07,270.38) v3(179.07,265.3) v3(179.07,260.22) v3(179.07,255.14) v3(179.07,250.06) v3(179.07,244.98) v3(179.07,239.9) v3(179.07,234.82) v3(179.07,229.74) v3(179.07,224.66) v3(179.07,219.58) v3(179.07,214.5) v3(179.07,209.42) v3(179.07,204.34) v3(179.07,199.26) v3(179.07,194.18) v3(179.07,153.54) v3(179.07,148.46) v3(179.07,143.38) v3(179.07,138.3) v3(184.15,295.78) v3(184.15,290.7) v3(184.15,285.62) v3(184.15,280.54) v3(184.15,275.46) v3(184.15,270.38) v3(184.15,265.3) v3(184.15,260.22) v3(184.15,255.14) v3(184.15,250.06) v3(184.15,244.98) v3(184.15,239.9) v3(184.15,234.82) v3(184.15,229.74) v3(184.15,224.66) v3(184.15,219.58) v3(184.15,214.5) v3(184.15,209.42) v3(184.15,204.34) v3(184.15,199.26) v3(184.15,194.18) v3(184.15,153.54) v3(184.15,148.46) v3(184.15,143.38) v3(184.15,138.3) v3(189.23,295.78) v3(189.23,290.7) v3(189.23,285.62) v3(189.23,280.54) v3(189.23,275.46) v3(189.23,270.38) v3(189.23,265.3) v3(189.23,260.22) v3(189.23,255.14) v3(189.23,250.06) v3(189.23,244.98) v3(189.23,239.9) v3(189.23,234.82) v3(189.23,229.74) v3(189.23,224.66) v3(189.23,219.58) v3(189.23,214.5) v3(189.23,209.42) v3(189.23,204.34) v3(189.23,199.26) v3(189.23,194.18) v3(189.23,189.1) v3(189.23,184.02) v3(189.23,178.94) v3(189.23,173.86) v3(189.23,153.54) v3(189.23,148.46) v3(189.23,143.38) v3(189.23,138.3) v3(194.31,295.78) v3(194.31,290.7) v3(194.31,285.62) v3(194.31,280.54) v3(194.31,275.46) v3(194.31,270.38) v3(194.31,265.3) v3(194.31,260.22) v3(194.31,255.14) v3(194.31,250.06) v3(194.31,244.98) v3(194.31,239.9) v3(194.31,234.82) v3(194.31,229.74) v3(194.31,224.66) v3(194.31,219.58) v3(194.31,214.5) v3(194.31,209.42) v3(194.31,204.34) v3(194.31,199.26) v3(194.31,194.18) v3(194.31,189.1) v3(194.31,184.02) v3(194.31,178.94) v3(194.31,173.86) v3(194.31,168.78) v3(194.31,163.7) v3(194.31,158.62) v3(194.31,153.54) v3(194.31,148.46) v3(194.31,143.38) v3(194.31,138.3) v3(199.39,295.78) v3(199.39,290.7) v3(199.39,285.62) v3(199.39,280.54) v3(199.39,275.46) v3(199.39,270.38) v3(199.39,265.3) v3(199.39,260.22) v3(199.39,255.14) v3(199.39,250.06) v3(199.39,244.98) v3(199.39,239.9) v3(199.39,234.82) v3(199.39,229.74) v3(199.39,224.66) v3(199.39,219.58) v3(199.39,214.5) v3(199.39,209.42) v3(199.39,204.34) v3(199.39,199.26) v3(199.39,194.18) v3(199.39,189.1) v3(199.39,184.02) v3(199.39,178.94) v3(199.39,173.86) v3(199.39,168.78) v3(199.39,163.7) v3(199.39,158.62) v3(199.39,153.54) v3(199.39,148.46) v3(199.39,143.38) v3(199.39,138.3) v3(204.47,295.78) v3(204.47,290.7) v3(204.47,285.62) v3(204.47,280.54) v3(204.47,275.46) v3(204.47,270.38) v3(204.47,265.3) v3(204.47,260.22) v3(204.47,255.14) v3(204.47,250.06) v3(204.47,244.98) v3(204.47,239.9) v3(204.47,234.82) v3(204.47,229.74) v3(204.47,224.66) v3(204.47,219.58) v3(204.47,214.5) v3(204.47,209.42) v3(204.47,204.34) v3(204.47,199.26) v3(204.47,194.18) v3(204.47,189.1) v3(204.47,184.02) v3(204.47,178.94) v3(204.47,173.86) v3(204.47,168.78) v3(204.47,163.7) v3(204.47,158.62) v3(204.47,153.54) v3(204.47,148.46) v3(204.47,143.38) v3(204.47,138.3) v3(209.55,290.7) v3(209.55,285.62) v3(209.55,280.54) v3(209.55,275.46) v3(209.55,270.38) v3(209.55,265.3) v3(209.55,260.22) v3(209.55,255.14) v3(209.55,250.06) v3(209.55,244.98) v3(209.55,239.9) v3(209.55,234.82) v3(209.55,229.74) v3(209.55,224.66) v3(209.55,219.58) v3(209.55,214.5) v3(209.55,209.42) v3(209.55,204.34) v3(209.55,199.26) v3(209.55,194.18) v3(209.55,189.1) v3(209.55,184.02) v3(209.55,178.94) v3(209.55,173.86) v3(209.55,168.78) v3(209.55,163.7) v3(209.55,158.62) v3(209.55,153.54) v3(209.55,148.46) v3(209.55,143.38) v3(209.55,138.3) v3(214.63,295.78) v3(214.63,275.46) v3(214.63,270.38) v3(214.63,265.3) v3(214.63,260.22) v3(214.63,255.14) v3(214.63,250.06) v3(214.63,244.98) v3(214.63,239.9) v3(214.63,234.82) v3(214.63,229.74) v3(214.63,224.66) v3(214.63,219.58) v3(214.63,214.5) v3(214.63,209.42) v3(214.63,204.34) v3(214.63,199.26) v3(214.63,194.18) v3(214.63,189.1) v3(214.63,184.02) v3(214.63,178.94) v3(214.63,173.86) v3(214.63,168.78) v3(214.63,163.7) v3(214.63,158.62) v3(214.63,153.54) v3(219.71,295.78) v3(219.71,275.46) v3(219.71,270.38) v3(219.71,265.3) v3(219.71,260.22) v3(219.71,255.14) v3(219.71,250.06) v3(219.71,244.98) v3(219.71,239.9) v3(219.71,234.82) v3(219.71,229.74) v3(219.71,224.66) v3(219.71,219.58) v3(219.71,214.5) v3(219.71,209.42) v3(219.71,204.34) v3(219.71,199.26) v3(219.71,194.18) v3(219.71,189.1) v3(219.71,184.02) v3(219.71,178.94) v3(219.71,173.86) v3(219.71,168.78) v3(219.71,163.7) v3(219.71,158.62) v3(219.71,153.54) v3(224.79,295.78) v3(224.79,275.46) v3(224.79,270.38) v3(224.79,265.3) v3(224.79,260.22) v3(224.79,255.14) v3(224.79,250.06) v3(224.79,244.98) v3(224.79,239.9) v3(224.79,234.82) v3(224.79,229.74) v3(224.79,224.66) v3(224.79,219.58) v3(224.79,214.5) v3(224.79,209.42) v3(224.79,204.34) v3(224.79,199.26) v3(224.79,194.18) v3(224.79,189.1) v3(224.79,184.02) v3(224.79,178.94) v3(224.79,173.86) v3(224.79,168.78) v3(224.79,163.7) v3(224.79,158.62) v3(224.79,153.54) v3(229.87,295.78) v3(229.87,290.7) v3(229.87,285.62) v3(229.87,280.54) v3(229.87,275.46) v3(229.87,270.38) v3(229.87,265.3) v3(229.87,260.22) v3(229.87,255.14) v3(229.87,250.06) v3(229.87,244.98) v3(229.87,239.9) v3(229.87,234.82) v3(229.87,229.74) v3(229.87,224.66) v3(229.87,219.58) v3(229.87,214.5) v3(229.87,209.42) v3(229.87,204.34) v3(229.87,199.26) v3(229.87,194.18) v3(229.87,189.1) v3(229.87,184.02) v3(229.87,178.94) v3(229.87,173.86) v3(229.87,168.78) v3(229.87,163.7) v3(229.87,158.62) v3(229.87,153.54) v3(229.87,148.46) v3(229.87,143.38) v3(229.87,138.3) v3(234.95,295.78) v3(234.95,290.7) v3(234.95,285.62) v3(234.95,260.22) v3(234.95,255.14) v3(234.95,250.06) v3(234.95,244.98) v3(234.95,239.9) v3(234.95,234.82) v3(234.95,229.74) v3(234.95,224.66) v3(234.95,219.58) v3(234.95,214.5) v3(234.95,209.42) v3(234.95,204.34) v3(234.95,199.26) v3(234.95,194.18) v3(234.95,189.1) v3(234.95,184.02) v3(234.95,178.94) v3(234.95,173.86) v3(234.95,168.78) v3(234.95,163.7) v3(234.95,158.62) v3(234.95,153.54) v3(234.95,148.46) v3(234.95,143.38) v3(234.95,138.3) v3(240.03,295.78) v3(240.03,290.7) v3(240.03,285.62) v3(240.03,260.22) v3(240.03,255.14) v3(240.03,250.06) v3(240.03,244.98) v3(240.03,239.9) v3(240.03,234.82) v3(240.03,229.74) v3(240.03,224.66) v3(240.03,219.58) v3(240.03,214.5) v3(240.03,209.42) v3(240.03,204.34) v3(240.03,199.26) v3(240.03,194.18) v3(240.03,189.1) v3(240.03,184.02) v3(240.03,178.94) v3(240.03,173.86) v3(240.03,168.78) v3(240.03,163.7) v3(240.03,158.62) v3(240.03,138.3) v3(245.11,295.78) v3(245.11,290.7) v3(245.11,285.62) v3(245.11,280.54) v3(245.11,275.46) v3(245.11,270.38) v3(245.11,265.3) v3(245.11,260.22) v3(245.11,255.14) v3(245.11,250.06) v3(245.11,244.98) v3(245.11,239.9) v3(245.11,234.82) v3(245.11,229.74) v3(245.11,224.66) v3(245.11,219.58) v3(245.11,214.5) v3(245.11,209.42) v3(245.11,204.34) v3(245.11,199.26) v3(245.11,194.18) v3(245.11,189.1) v3(245.11,184.02) v3(245.11,178.94) v3(245.11,173.86) v3(245.11,168.78) v3(245.11,163.7) v3(245.11,158.62) v3(245.11,138.3) v3(250.19,295.78) v3(250.19,290.7) v3(250.19,285.62) v3(250.19,260.22) v3(250.19,255.14) v3(250.19,250.06) v3(250.19,244.98) v3(250.19,239.9) v3(250.19,234.82) v3(250.19,204.34) v3(250.19,199.26) v3(250.19,168.78) v3(250.19,163.7) v3(250.19,158.62) v3(250.19,138.3) v3(255.27,295.78) v3(255.27,290.7) v3(255.27,285.62) v3(255.27,260.22) v3(255.27,255.14) v3(255.27,250.06) v3(255.27,244.98) v3(255.27,239.9) v3(255.27,234.82) v3(255.27,229.74) v3(255.27,224.66) v3(255.27,219.58) v3(255.27,214.5) v3(255.27,199.26) v3(255.27,194.18) v3(255.27,189.1) v3(255.27,184.02) v3(255.27,178.94) v3(255.27,173.86) v3(255.27,168.78) v3(255.27,163.7) v3(255.27,158.62) v3(255.27,138.3) v3(260.35,295.78) v3(260.35,290.7) v3(260.35,285.62) v3(260.35,280.54) v3(260.35,275.46) v3(260.35,270.38) v3(260.35,265.3) v3(260.35,260.22) v3(260.35,255.14) v3(260.35,250.06) v3(260.35,244.98) v3(260.35,239.9) v3(260.35,234.82) v3(260.35,229.74) v3(260.35,224.66) v3(260.35,219.58) v3(260.35,214.5) v3(260.35,199.26) v3(260.35,194.18) v3(260.35,189.1) v3(260.35,184.02) v3(260.35,178.94) v3(260.35,173.86) v3(260.35,168.78) v3(260.35,163.7) v3(260.35,158.62) v3(260.35,138.3) v3(265.43,295.78) v3(265.43,290.7) v3(265.43,285.62) v3(265.43,260.22) v3(265.43,255.14) v3(265.43,250.06) v3(265.43,244.98) v3(265.43,224.66) v3(265.43,219.58) v3(265.43,184.02) v3(265.43,178.94) v3(265.43,173.86) v3(265.43,163.7) v3(265.43,158.62) v3(265.43,138.3) v3(270.51,295.78) v3(270.51,290.7) v3(270.51,285.62) v3(270.51,260.22) v3(270.51,255.14) v3(270.51,250.06) v3(270.51,244.98) v3(270.51,224.66) v3(270.51,184.02) v3(270.51,178.94) v3(270.51,173.86) v3(270.51,163.7) v3(270.51,158.62) v3(270.51,138.3) v3(275.59,295.78) v3(275.59,290.7) v3(275.59,285.62) v3(275.59,280.54) v3(275.59,275.46) v3(275.59,270.38) v3(275.59,265.3) v3(275.59,260.22) v3(275.59,255.14) v3(275.59,250.06) v3(275.59,244.98) v3(275.59,184.02) v3(275.59,178.94) v3(275.59,173.86) v3(275.59,168.78) v3(275.59,163.7) v3(275.59,158.62) v3(275.59,153.54) v3(275.59,138.3) v3(280.67,295.78) v3(280.67,290.7) v3(280.67,285.62) v3(280.67,260.22) v3(280.67,255.14) v3(280.67,234.82) v3(280.67,194.18) v3(280.67,173.86) v3(280.67,168.78) v3(280.67,163.7) v3(280.67,158.62) v3(280.67,138.3) v3(285.75,295.78) v3(285.75,290.7) v3(285.75,285.62) v3(285.75,260.22) v3(285.75,255.14) v3(285.75,173.86) v3(285.75,168.78) v3(285.75,163.7) v3(285.75,158.62) v3(285.75,138.3) v3(290.83,290.7) v3(290.83,285.62) v3(290.83,280.54) v3(290.83,275.46) v3(290.83,270.38) v3(290.83,265.3) v3(290.83,260.22) v3(290.83,255.14) v3(290.83,173.86) v3(290.83,168.78) v3(290.83,163.7) v3(290.83,158.62) v3(290.83,138.3) v3(295.91,295.78) v3(295.91,290.7) v3(295.91,285.62) v3(295.91,260.22) v3(295.91,255.14) v3(295.91,173.86) v3(295.91,168.78) v3(295.91,163.7) v3(295.91,158.62) v3(295.91,138.3) v3(300.99,295.78) v3(300.99,290.7) v3(300.99,285.62) v3(300.99,260.22) v3(300.99,255.14) v3(300.99,163.7) v3(300.99,158.62) v3(300.99,138.3) v3(306.07,295.78) v3(306.07,290.7) v3(306.07,285.62) v3(306.07,280.54) v3(306.07,275.46) v3(306.07,270.38) v3(306.07,265.3) v3(306.07,260.22) v3(306.07,255.14) v3(306.07,250.06) v3(306.07,244.98) v3(306.07,184.02) v3(306.07,178.94) v3(306.07,173.86) v3(306.07,168.78) v3(306.07,163.7) v3(306.07,158.62) v3(306.07,138.3) v3(311.15,295.78) v3(311.15,290.7) v3(311.15,285.62) v3(311.15,260.22) v3(311.15,255.14) v3(311.15,250.06) v3(311.15,244.98) v3(311.15,184.02) v3(311.15,178.94) v3(311.15,173.86) v3(311.15,168.78) v3(311.15,138.3) v3(316.23,295.78) v3(316.23,290.7) v3(316.23,285.62) v3(316.23,260.22) v3(316.23,255.14) v3(316.23,250.06) v3(316.23,244.98) v3(316.23,209.42) v3(316.23,204.34) v3(316.23,184.02) v3(316.23,178.94) v3(316.23,173.86) v3(316.23,138.3) v3(321.31,295.78) v3(321.31,290.7) v3(321.31,285.62) v3(321.31,280.54) v3(321.31,275.46) v3(321.31,270.38) v3(321.31,265.3) v3(321.31,260.22) v3(321.31,255.14) v3(321.31,250.06) v3(321.31,239.9) v3(321.31,224.66) v3(321.31,178.94) v3(321.31,173.86) v3(321.31,138.3) v3(326.39,295.78) v3(326.39,290.7) v3(326.39,285.62) v3(326.39,260.22) v3(326.39,189.1) v3(326.39,184.02) v3(326.39,178.94) v3(326.39,173.86) v3(326.39,153.54) v3(326.39,148.46) v3(326.39,143.38) v3(326.39,138.3) v3(331.47,295.78) v3(331.47,290.7) v3(331.47,285.62) v3(331.47,260.22) v3(331.47,189.1) v3(331.47,184.02) v3(331.47,178.94) v3(331.47,173.86) v3(331.47,153.54) v3(331.47,148.46) v3(331.47,143.38) v3(331.47,138.3) v3(336.55,295.78) v3(336.55,290.7) v3(336.55,285.62) v3(336.55,280.54) v3(336.55,275.46) v3(336.55,270.38) v3(336.55,265.3) v3(336.55,260.22) v3(336.55,255.14) v3(336.55,239.9) v3(336.55,234.82) v3(336.55,219.58) v3(336.55,214.5) v3(336.55,194.18) v3(336.55,184.02) v3(336.55,178.94) v3(336.55,173.86) v3(336.55,153.54) v3(336.55,148.46) v3(336.55,143.38) v3(336.55,138.3) v3(341.63,295.78) v3(341.63,290.7) v3(341.63,285.62) v3(341.63,260.22) v3(341.63,255.14) v3(341.63,219.58) v3(341.63,214.5) v3(341.63,209.42) v3(341.63,204.34) v3(341.63,199.26) v3(341.63,194.18) v3(341.63,189.1) v3(341.63,184.02) v3(341.63,178.94) v3(341.63,173.86) v3(341.63,153.54) v3(341.63,148.46) v3(341.63,143.38) v3(341.63,138.3) v3(346.71,295.78) v3(346.71,290.7) v3(346.71,285.62) v3(346.71,260.22) v3(346.71,255.14) v3(346.71,214.5) v3(346.71,209.42) v3(346.71,204.34) v3(346.71,199.26) v3(346.71,194.18) v3(346.71,189.1) v3(346.71,184.02) v3(346.71,178.94) v3(346.71,173.86) v3(346.71,153.54) v3(346.71,148.46) v3(346.71,143.38) v3(346.71,138.3) v3(351.79,295.78) v3(351.79,290.7) v3(351.79,285.62) v3(351.79,280.54) v3(351.79,275.46) v3(351.79,270.38) v3(351.79,265.3) v3(351.79,260.22) v3(351.79,255.14) v3(351.79,219.58) v3(351.79,214.5) v3(351.79,194.18) v3(351.79,189.1) v3(351.79,184.02) v3(351.79,178.94) v3(351.79,173.86) v3(351.79,168.78) v3(351.79,153.54) v3(351.79,148.46) v3(351.79,143.38) v3(351.79,138.3) v3(356.87,295.78) v3(356.87,275.46) v3(356.87,270.38) v3(356.87,265.3) v3(356.87,260.22) v3(356.87,255.14) v3(356.87,234.82) v3(356.87,219.58) v3(356.87,214.5) v3(356.87,204.34) v3(356.87,199.26) v3(356.87,194.18) v3(356.87,189.1) v3(356.87,184.02) v3(356.87,178.94) v3(356.87,173.86) v3(356.87,153.54) v3(361.95,295.78) v3(361.95,275.46) v3(361.95,270.38) v3(361.95,265.3) v3(361.95,260.22) v3(361.95,255.14) v3(361.95,250.06) v3(361.95,229.74) v3(361.95,224.66) v3(361.95,214.5) v3(361.95,209.42) v3(361.95,204.34) v3(361.95,199.26) v3(361.95,194.18) v3(361.95,189.1) v3(361.95,184.02) v3(361.95,178.94) v3(361.95,173.86) v3(361.95,153.54) v3(367.03,295.78) v3(367.03,275.46) v3(367.03,270.38) v3(367.03,265.3) v3(367.03,260.22) v3(367.03,255.14) v3(367.03,250.06) v3(367.03,229.74) v3(367.03,224.66) v3(367.03,219.58) v3(367.03,214.5) v3(367.03,209.42) v3(367.03,204.34) v3(367.03,199.26) v3(367.03,194.18) v3(367.03,189.1) v3(367.03,184.02) v3(367.03,178.94) v3(367.03,173.86) v3(367.03,153.54) v3(372.11,295.78) v3(372.11,290.7) v3(372.11,285.62) v3(372.11,280.54) v3(372.11,275.46) v3(372.11,270.38) v3(372.11,265.3) v3(372.11,260.22) v3(372.11,255.14) v3(372.11,250.06) v3(372.11,229.74) v3(372.11,224.66) v3(372.11,219.58) v3(372.11,214.5) v3(372.11,204.34) v3(372.11,158.62) v3(372.11,153.54) v3(372.11,148.46) v3(372.11,143.38) v3(372.11,138.3) v3(377.19,295.78) v3(377.19,290.7) v3(377.19,285.62) v3(377.19,280.54) v3(377.19,275.46) v3(377.19,270.38) v3(377.19,265.3) v3(377.19,260.22) v3(377.19,255.14) v3(377.19,250.06) v3(377.19,244.98) v3(377.19,239.9) v3(377.19,234.82) v3(377.19,229.74) v3(377.19,224.66) v3(377.19,219.58) v3(377.19,158.62) v3(377.19,153.54) v3(377.19,148.46) v3(377.19,143.38) v3(377.19,138.3) v3(382.27,295.78) v3(382.27,290.7) v3(382.27,285.62) v3(382.27,280.54) v3(382.27,275.46) v3(382.27,270.38) v3(382.27,265.3) v3(382.27,260.22) v3(382.27,255.14) v3(382.27,250.06) v3(382.27,244.98) v3(382.27,239.9) v3(382.27,234.82) v3(382.27,229.74) v3(382.27,224.66) v3(382.27,219.58) v3(382.27,158.62) v3(382.27,153.54) v3(382.27,148.46) v3(382.27,143.38) v3(382.27,138.3) v3(387.35,295.78) v3(387.35,290.7) v3(387.35,285.62) v3(387.35,280.54) v3(387.35,275.46) v3(387.35,270.38) v3(387.35,265.3) v3(387.35,260.22) v3(387.35,255.14) v3(387.35,239.9) v3(387.35,234.82) v3(387.35,214.5) v3(387.35,209.42) v3(387.35,204.34) v3(387.35,199.26) v3(387.35,194.18) v3(387.35,189.1) v3(387.35,184.02) v3(387.35,178.94) v3(387.35,173.86) v3(387.35,168.78) v3(387.35,163.7) v3(387.35,158.62) v3(387.35,153.54) v3(387.35,148.46) v3(387.35,143.38) v3(387.35,138.3) v3(392.43,295.78) v3(392.43,290.7) v3(392.43,285.62) v3(392.43,280.54) v3(392.43,275.46) v3(392.43,270.38) v3(392.43,265.3) v3(392.43,260.22) v3(392.43,214.5) v3(392.43,209.42) v3(392.43,204.34) v3(392.43,199.26) v3(392.43,194.18) v3(392.43,189.1) v3(392.43,184.02) v3(392.43,178.94) v3(392.43,173.86) v3(392.43,168.78) v3(392.43,163.7) v3(392.43,158.62) v3(392.43,153.54) v3(392.43,148.46) v3(392.43,143.38) v3(392.43,138.3) v3(397.51,295.78) v3(397.51,290.7) v3(397.51,285.62) v3(397.51,280.54) v3(397.51,275.46) v3(397.51,270.38) v3(397.51,265.3) v3(397.51,260.22) v3(397.51,209.42) v3(397.51,204.34) v3(397.51,199.26) v3(397.51,194.18) v3(397.51,189.1) v3(397.51,184.02) v3(397.51,178.94) v3(397.51,173.86) v3(397.51,168.78) v3(397.51,163.7) v3(397.51,158.62) v3(397.51,153.54) v3(397.51,148.46) v3(397.51,143.38) v3(397.51,138.3) v3(402.59,295.78) v3(402.59,290.7) v3(402.59,285.62) v3(402.59,280.54) v3(402.59,275.46) v3(402.59,270.38) v3(402.59,265.3) v3(402.59,260.22) v3(402.59,209.42) v3(402.59,204.34) v3(402.59,199.26) v3(402.59,194.18) v3(402.59,189.1) v3(402.59,184.02) v3(402.59,178.94) v3(402.59,173.86) v3(402.59,168.78) v3(402.59,163.7) v3(402.59,158.62) v3(402.59,153.54) v3(402.59,148.46) v3(402.59,143.38) v3(402.59,138.3) v3(407.67,295.78) v3(407.67,290.7) v3(407.67,285.62) v3(407.67,280.54) v3(407.67,275.46) v3(407.67,270.38) v3(407.67,265.3) v3(407.67,260.22) v3(407.67,255.14) v3(407.67,250.06) v3(407.67,244.98) v3(407.67,239.9) v3(407.67,234.82) v3(407.67,229.74) v3(407.67,224.66) v3(407.67,219.58) v3(407.67,214.5) v3(407.67,209.42) v3(407.67,204.34) v3(407.67,199.26) v3(407.67,194.18) v3(407.67,189.1) v3(407.67,184.02) v3(407.67,178.94) v3(407.67,173.86) v3(407.67,168.78) v3(407.67,163.7) v3(407.67,158.62) v3(407.67,153.54) v3(407.67,148.46) v3(407.67,143.38) v3(407.67,138.3) v3(412.75,295.78) v3(412.75,290.7) v3(412.75,285.62) v3(412.75,280.54) v3(412.75,275.46) v3(412.75,270.38) v3(412.75,265.3) v3(412.75,260.22) v3(412.75,255.14) v3(412.75,250.06) v3(412.75,244.98) v3(412.75,239.9) v3(412.75,234.82) v3(412.75,229.74) v3(412.75,224.66) v3(412.75,219.58) v3(412.75,214.5) v3(412.75,209.42) v3(412.75,204.34) v3(412.75,199.26) v3(412.75,194.18) v3(412.75,189.1) v3(412.75,184.02) v3(412.75,178.94) v3(412.75,173.86) v3(412.75,168.78) v3(412.75,163.7) v3(412.75,158.62) v3(412.75,153.54) v3(412.75,148.46) v3(412.75,143.38) v3(412.75,138.3) v3(417.83,295.78) v3(417.83,290.7) v3(417.83,285.62) v3(417.83,280.54) v3(417.83,275.46) v3(417.83,270.38) v3(417.83,265.3) v3(417.83,260.22) v3(417.83,255.14) v3(417.83,250.06) v3(417.83,244.98) v3(417.83,239.9) v3(417.83,234.82) v3(417.83,194.18) v3(417.83,189.1) v3(417.83,184.02) v3(417.83,178.94) v3(417.83,173.86) v3(417.83,168.78) v3(417.83,163.7) v3(417.83,158.62) v3(417.83,153.54) v3(417.83,148.46) v3(417.83,143.38) v3(417.83,138.3) v3(422.91,295.78) v3(422.91,290.7) v3(422.91,280.54) v3(422.91,275.46) v3(422.91,270.38) v3(422.91,265.3) v3(422.91,260.22) v3(422.91,255.14) v3(422.91,250.06) v3(422.91,244.98) v3(422.91,239.9) v3(422.91,189.1) v3(422.91,184.02) v3(422.91,178.94) v3(422.91,173.86) v3(422.91,168.78) v3(422.91,163.7) v3(422.91,158.62) v3(422.91,153.54) v3(422.91,148.46) v3(422.91,143.38) v3(422.91,138.3) v4(33.4,213.61)
